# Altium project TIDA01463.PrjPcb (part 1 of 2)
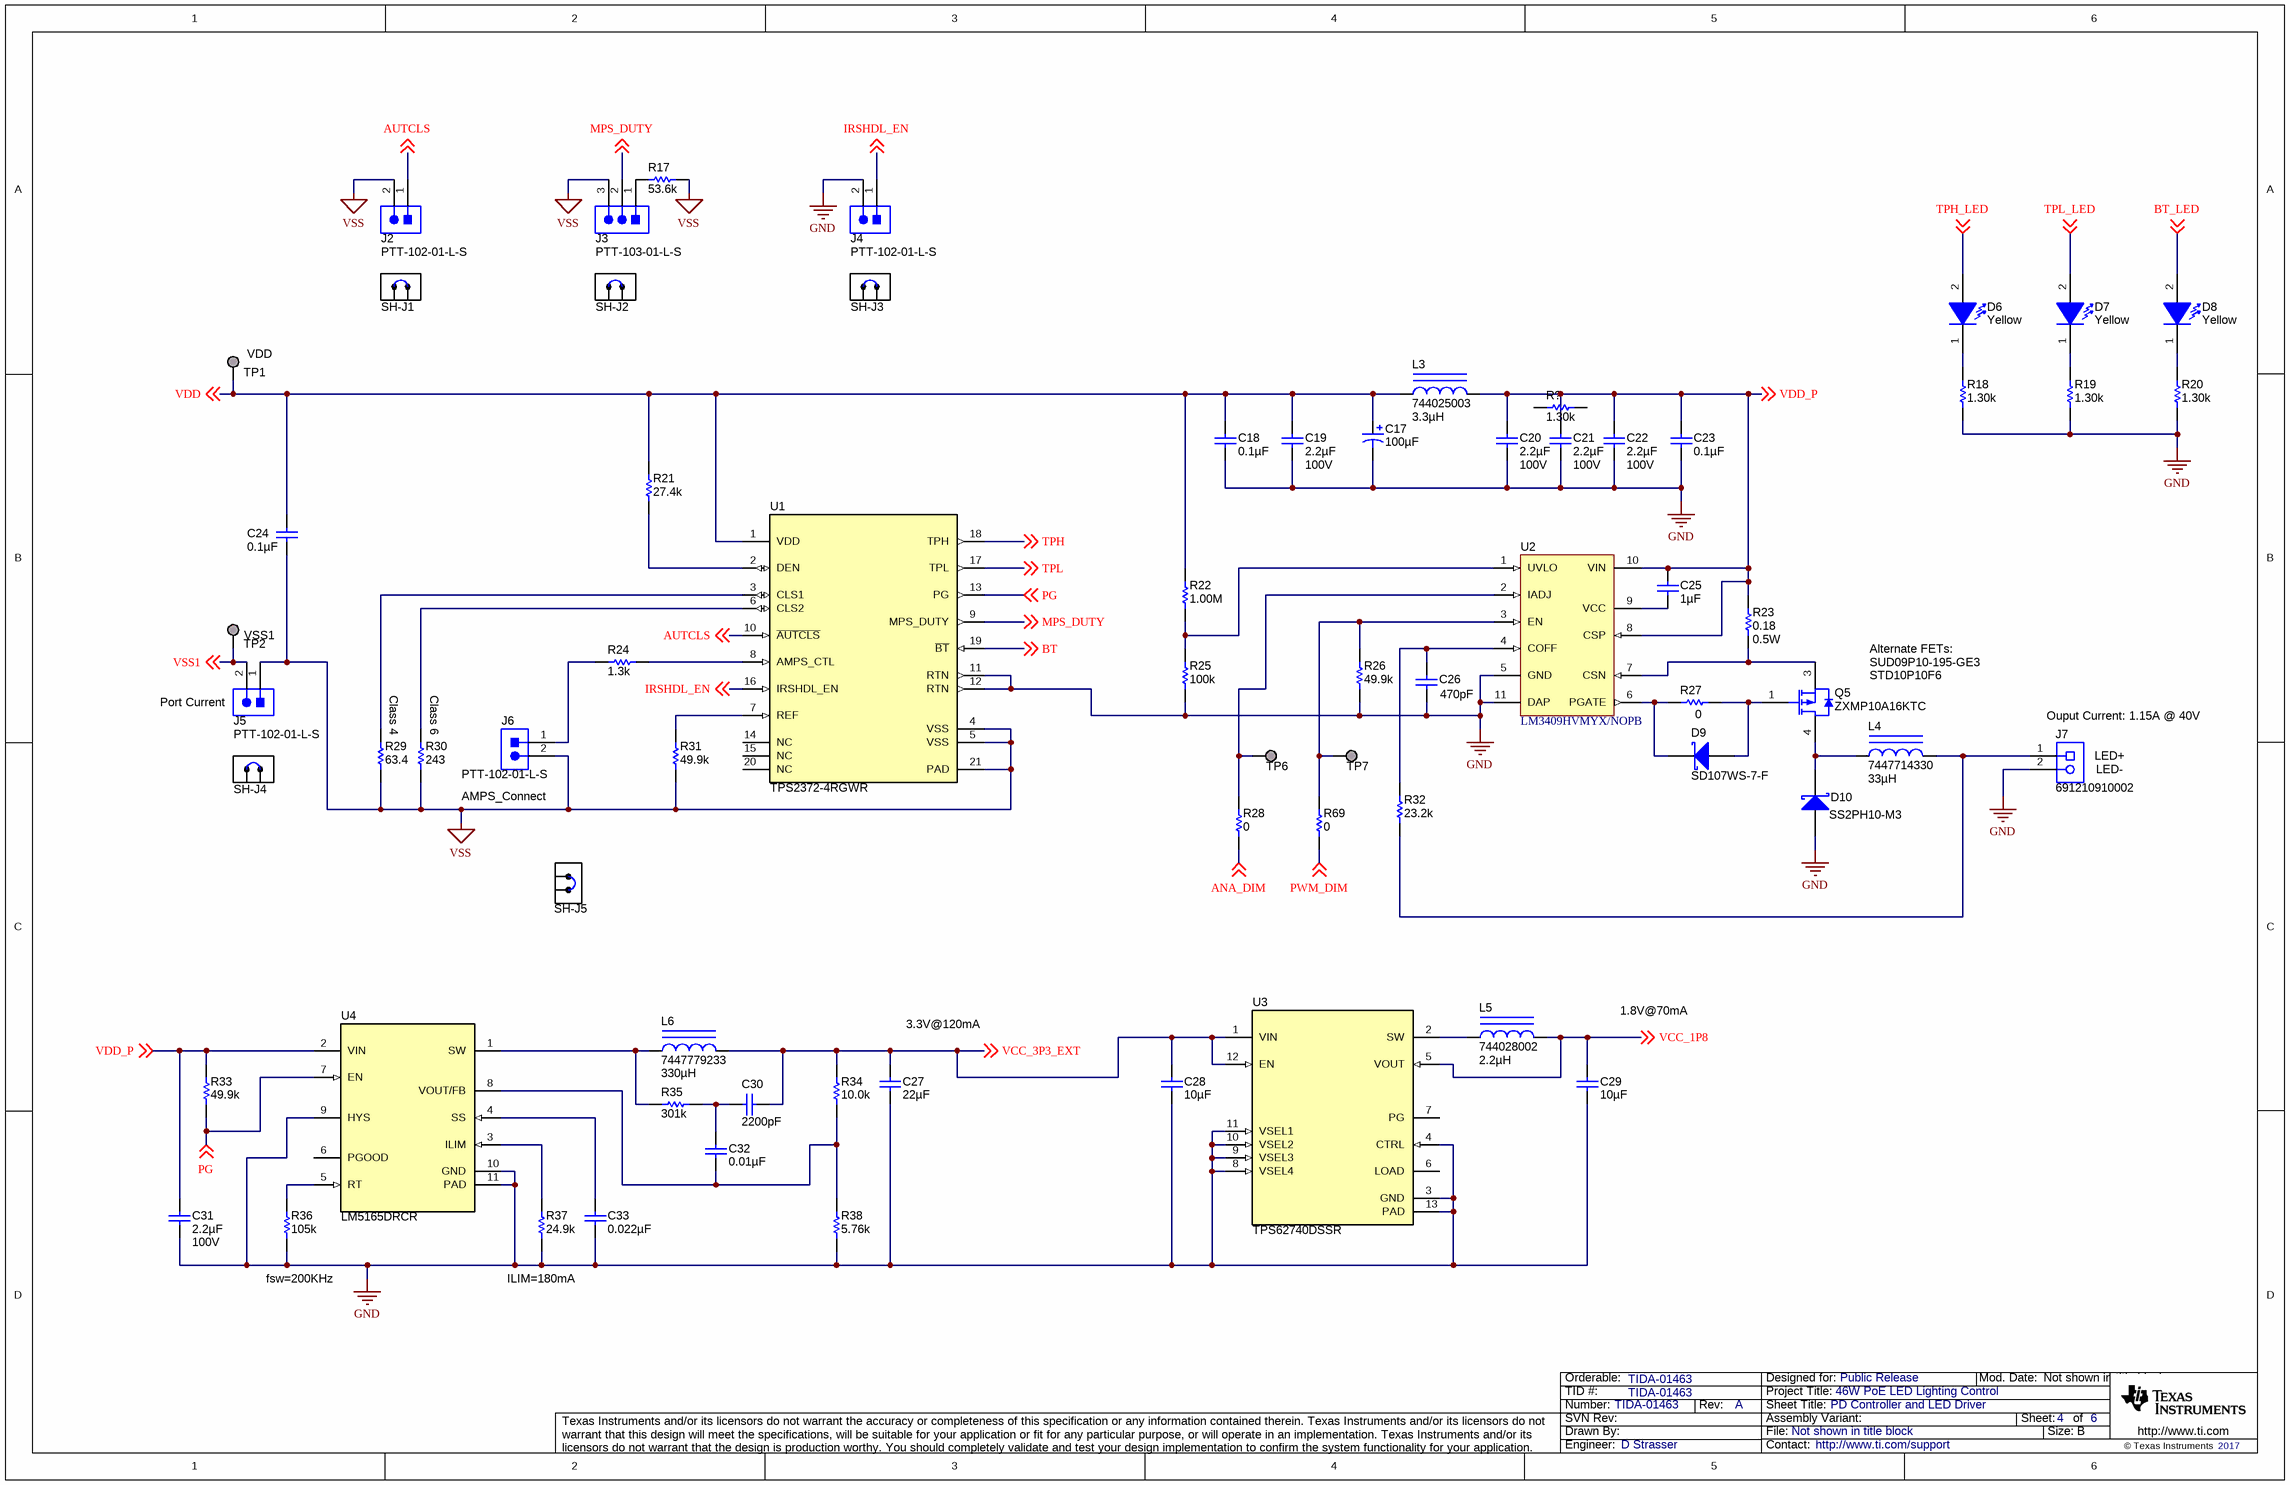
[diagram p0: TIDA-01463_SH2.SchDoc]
TID: TIDA-01463; TechSupport: http://www.ti.com/support; SCH_Rev: A; PRJ_Title: 46W PoE LED Lighting Control; PRJ_Number: TIDA-01463; PRJ_Engineer: D Strasser; PRJ_Customer: Public Release; PCB_Rev: A; PCB_Layout: D Strasser; EVM_orderable: TIDA-01463; CopyrightYear: 2017
5 sheets, 210 parts. Net scope: global (net labels, ports and power ports of the same name join across sheets).
Board file: TIDA-01463.PcbDoc
Sheets:
  TIDA-01463_SH2.SchDoc
  TIDA-01463_EVM_Hardware.SchDoc
  TIDA-01463_SH3.SchDoc
  TIDA-01463_SH4.SchDoc
  TIDA-01463_SH1.SchDoc

## Sheet TIDA-01463_SH2.SchDoc: PD Controller and LED Driver
size 431 x 279 mm; Date: Not shown in title block; ApprovedBy: Not shown in title block; CheckedBy: Not shown in title block; Author: Not shown in title block; CompanyName: Not shown in title block; Engineer: Not shown in title block; Organization: Not shown in title block; Address1: Not shown in title block; Address2: Not shown in title block; Address3: Not shown in title block; Address4: Not shown in title block; DocumentNumber: 4; Revision: Use project parameter SCH_Rev; SheetNumber: 4; SheetTotal: 6; PageSetup: Record=PageOptions¦CenterHorizontal=True¦CenterVertical=True¦PrintScale=1.00¦XCorrection=1.00¦YCorrection=1.00¦PrintKind=0¦BorderSize=5000000¦LeftOffset=0¦BottomOffset=0¦Orientation=2¦PaperLength=1000¦PaperWidth=1000¦Scale=100¦PaperSource=15¦PrintQuality=600¦MediaType=1¦DitherType=10¦PaperKind=Letter¦PrintScaleMode=1

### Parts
C17  ValueDisplayed: 100µF  [SM_RADIAL_J16]  (hidden comment: EEV-FK2A101M)
C18  ValueDisplayed: 0.1µF  [0805L]  (hidden comment: C0805C104K1RACTU)
C19  ValueDisplayed: 2.2µF  Value2: 100V  [1210_210L]  (hidden comment: C1210C225K1RACTU)
C20  ValueDisplayed: 2.2µF  Value2: 100V  [1210_210L]  (hidden comment: C1210C225K1RACTU)
C21  ValueDisplayed: 2.2µF  Value2: 100V  [1210_210L]  (hidden comment: C1210C225K1RACTU)
C22  ValueDisplayed: 2.2µF  Value2: 100V  [1210_210L]  (hidden comment: C1210C225K1RACTU)
C23  ValueDisplayed: 0.1µF  [0805_HV]  (hidden comment: C0805C104K1RACTU)
C24  ValueDisplayed: 0.1µF  [0805L]  (hidden comment: C0805C104K1RACTU)
C25  ValueDisplayed: 1µF  [0603L]  (hidden comment: 885012206052)
C26  ValueDisplayed: 470pF  [0603L]  (hidden comment: 06035A471JAT2A)
C27  ValueDisplayed: 22µF  [0805L]  (hidden comment: GRM21BR60J226ME39L)
C28  ValueDisplayed: 10µF  [0603L]  (hidden comment: GRM188R60J106ME47D)
C29  ValueDisplayed: 10µF  [0603L]  (hidden comment: GRM188R60J106ME47D)
C30  ValueDisplayed: 2200pF  [0603L]  (hidden comment: 885012206036)
C31  ValueDisplayed: 2.2µF  Value2: 100V  [1210_210L]  (hidden comment: C1210C225K1RACTU)
C32  ValueDisplayed: 0.01µF  [0603L]  (hidden comment: 885012206040)
C33  ValueDisplayed: 0.022µF  [0603L]  (hidden comment: 885012206091)
D6  value Yellow  [WL-SMCW_YELLOW]  (hidden comment: 150060YS75000)
D7  value Yellow  [WL-SMCW_YELLOW]  (hidden comment: 150060YS75000)
D8  value Yellow  [WL-SMCW_YELLOW]  (hidden comment: 150060YS75000)
D9  SD107WS-7-F  [sod-323]
D10  SS2PH10-M3  [DO-220AA]
J2  PTT-102-01-L-S  [Samtec_PTT-102-01-x-S]
J3  PTT-103-01-L-S  [Samtec_PTT-103-01-x-S]
J4  PTT-102-01-L-S  [Samtec_PTT-102-01-x-S]
J5  PTT-102-01-L-S  [Samtec_PTT-102-01-x-S]
J6  PTT-102-01-L-S  [Samtec_PTT-102-01-x-S]
J7  691210910002  [Wurth_691210910002]
L3  744025003  ValueDisplayed: 3.3µH  [WE-TPC_2828]
L4  7447714330  ValueDisplayed: 33µH  [WE-PD_1050]
L5  744028002  ValueDisplayed: 2.2µH  [WE-TPC-T]
L6  7447779233  ValueDisplayed: 330µH  [WE-PD_7345_PlasticBase]
Q5  ZXMP10A16KTC  [DPAK]
R17  ValueDisplayed: 53.6k  [0603L]  (hidden comment: CRCW060353K6FKEA)
R18  ValueDisplayed: 1.30k  [0603]  (hidden comment: RC0603FR-071K3L)
R19  ValueDisplayed: 1.30k  [0603]  (hidden comment: RC0603FR-071K3L)
R20  ValueDisplayed: 1.30k  [0603]  (hidden comment: RC0603FR-071K3L)
R21  ValueDisplayed: 27.4k  [0603L]  (hidden comment: CRCW060327K4FKEA)
R22  ValueDisplayed: 1.00M  [0402]  (hidden comment: CRCW04021M00FKED)
R23  ValueDisplayed: 0.18  Value2: 0.5W  [1210L]  (hidden comment: MCR25JZHFLR180)
R24  ValueDisplayed: 1.3k  [0805_HV]  (hidden comment: ERJ-6GEYJ132V)
R25  ValueDisplayed: 100k  [0402]  (hidden comment: CRCW0402100KFKED)
R26  ValueDisplayed: 49.9k  [0603L]  (hidden comment: CRCW060349K9FKEA)
R27  ValueDisplayed: 0  [0603L]  (hidden comment: CRCW06030000Z0EA)
R28  ValueDisplayed: 0  [0402]  (hidden comment: ERJ-2GE0R00X)
R29  ValueDisplayed: 63.4  [0603]  (hidden comment: RC0603FR-0763R4L)
R30  ValueDisplayed: 243  [0603]  (hidden comment: RC0603FR-07243RL)
R31  ValueDisplayed: 49.9k  [0603L]  (hidden comment: CRCW060349K9FKEA)
R32  ValueDisplayed: 23.2k  [0603L]  (hidden comment: CRCW060323K2FKEA)
R33  ValueDisplayed: 49.9k  [0603L]  (hidden comment: CRCW060349K9FKEA)
R34  ValueDisplayed: 10.0k  [0402]  (hidden comment: CRCW040210K0FKED)
R35  ValueDisplayed: 301k  [0603L]  (hidden comment: CRCW0603301KFKEA)
R36  ValueDisplayed: 105k  [0402]  (hidden comment: CRCW0402105KFKED)
R37  ValueDisplayed: 24.9k  [0402]  (hidden comment: CRCW040224K9FKED)
R38  ValueDisplayed: 5.76k  [0402]  (hidden comment: CRCW04025K76FKED)
R69  ValueDisplayed: 0  [0402]  (hidden comment: ERJ-2GE0R00X)
R?  ValueDisplayed: 1.30k  [0603]  (hidden comment: RC0603FR-071K3L)
SH-J1  2SN-BK-G  [2SN-BK-G]  (value not drawn)
SH-J2  2SN-BK-G  [2SN-BK-G]  (value not drawn)
SH-J3  2SN-BK-G  [2SN-BK-G]  (value not drawn)
SH-J4  2SN-BK-G  [2SN-BK-G]  (value not drawn)
SH-J5  2SN-BK-G  [2SN-BK-G]  (value not drawn)
TP1  TESTPOINT  [Keystone_5019]  (value not drawn)
TP2  TESTPOINT  [Keystone_5019]  (value not drawn)
TP6  TESTPOINT  [PAD_1MM_SQUARE]  (value not drawn)  (no BOM)
TP7  TESTPOINT  [PAD_1MM_SQUARE]  (value not drawn)  (no BOM)
U1  TPS2372-4RGWR  [RGW0020B]
U2  LM3409HVMYX/NOPB  [MUC10A_N]
U3  TPS62740DSSR  [DSS0012A]
U4  LM5165DRCR  [DRC0010J]

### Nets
GND: C17.2(-) C18.2 C19.2 C20.2 C21.2 C22.2 C23.2 C26.2 C27.2 C28.2 C29.2 C31.2 C33.2 D10.2(A) J4.2 J7.2 R18.1 R19.1 R20.1 R25.1 R26.1 R36.1 R37.1 R38.1 U1.11(RTN) U1.12(RTN) U2.5(GND) U2.11(DAP) U3.3(GND) U3.4(CTRL) U3.8(VSEL4) U3.9(VSEL3) U3.10(VSEL2) U3.11(VSEL1) U3.13(PAD) U4.9(HYS) U4.10(GND) U4.11(PAD)
VSS: C24.2 J2.2 J3.3 J5.1 J6.2 R17.2 R29.1 R30.1 R31.2 U1.4(VSS) U1.5(VSS) U1.21(PAD)
ANA_DIM: R28.1 ; off-sheet ANA_DIM
AUTCLS: J2.1 U1.10(~{AUTCLS}) ; off-sheet AUTCLS
BT: U1.19(~{BT}) ; off-sheet BT
BT_LED: D8.2(A) ; off-sheet BT_LED
IRSHDL_EN: J4.1 U1.16(IRSHDL_EN) ; off-sheet IRSHDL_EN
MPS_DUTY: J3.2 U1.9(MPS_DUTY) ; off-sheet MPS_DUTY
PG: R33.1 U1.13(PG) U4.7(EN) ; off-sheet PG
PWM_DIM: R69.1 ; off-sheet PWM_DIM
TPH: U1.18(TPH) ; off-sheet TPH
TPH_LED: D6.2(A) ; off-sheet TPH_LED
TPL: U1.17(TPL) ; off-sheet TPL
TPL_LED: D7.2(A) ; off-sheet TPL_LED
VCC_1P8: C29.1 L5.2 U3.5(VOUT) ; off-sheet VCC_1P8
VCC_3P3_EXT: C27.1 C28.1 C30.1 L6.2 R34.2 U3.1(VIN) U3.12(EN) ; off-sheet VCC_3P3_EXT
VDD: C17.1(+) C18.1 C19.1 C24.1 L3.1 R21.2 R22.2 TP1.1 U1.1(VDD) ; off-sheet VDD
VDD_P: C20.1 C21.1 C22.1 C23.1 C25.1 C31.1 L3.2 R23.2 R33.2 U2.8(CSP) U2.10(VIN) U4.2(VIN) ; off-sheet VDD_P
VSS1: J5.2 TP2.1 ; off-sheet VSS1
NetC25_2: C25.2 U2.9(VCC)
NetC26_1: C26.1 R32.2 U2.4(COFF)
NetC30_2: C30.2 C32.1 R35.2
NetC32_2: C32.2 R34.1 R38.2 U4.8(VOUT/FB)
NetC33_1: C33.1 U4.4(SS)
NetD6_1: D6.1(K) R18.2
NetD7_1: D7.1(K) R19.2
NetD8_1: D8.1(K) R20.2
NetD9_1: D9.1(K) R27.1 U2.6(PGATE)
NetD9_2: D9.2(A) Q5.1(G) R27.2
NetD10_1: D10.1(K) L4.1 Q5.4(D)
NetJ3_1: J3.1 R17.1
NetJ6_1: J6.1 R24.1
NetJ7_1: J7.1 L4.2 R32.1
NetL5_1: L5.1 U3.2(SW)
NetL6_1: L6.1 R35.1 U4.1(SW)
NetQ5_3: Q5.3(S) R23.1 U2.7(CSN)
NetR21_1: R21.1 U1.2(DEN)
NetR22_1: R22.1 R25.2 U2.1(UVLO)
NetR24_2: R24.2 U1.8(AMPS_CTL)
NetR26_2: R26.2 R69.2 TP7.1 U2.3(EN)
NetR28_2: R28.2 TP6.1 U2.2(IADJ)
NetR29_2: R29.2 U1.3(CLS1)
NetR30_2: R30.2 U1.6(CLS2)
NetR31_1: R31.1 U1.7(REF)
NetR36_2: R36.2 U4.5(RT)
NetR37_2: R37.2 U4.3(ILIM)

Not connected (* = marked no-connect by the designer): R? 1 2; U1 14(NC) 15(NC) 20(NC); U3 6(LOAD) 7(PG); U4 6(PGOOD)

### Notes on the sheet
- (near TP1) VDD
- (near TP2) VSS1
- (near J5) Port Current
- Alternate FETs:
- SUD09P10-195-GE3
- STD10P10F6
- (near R29) Class 4
- (near R30) Class 6
- (near J7) LED-
- (near J7) LED+
- (near J7) Ouput Current: 1.15A @ 40V
- AMPS_Connect
- (near C27) 3.3V@120mA
- 1.8V@70mA
- (near R36) fsw=200KHz
- ILIM=180mA

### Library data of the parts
C17 = EEV-FK2A101M: CAP, AL, 100 µF, 100 V, +/- 20%, 0.17 ohm, SMD; Manufacturer: Panasonic; Polarized: Y; CompType: Capacitor; Value: 100uF; U/M: EA; Cap_F: 0.0001; Tolerance_%: 20; VDC_V: 100; Value2: 100V; ESR_ohm: 0.17; IRMS_A: 0.793; TaMin_C: -55; TaMax_C: 105; Cap_Case: J16; AEC Category: Q200
C18 C23 C24 = C0805C104K1RACTU: CAP, CERM, 0.1 µF, 100 V, +/- 10%, X7R, 0805; Manufacturer: Kemet; Polarized: N; CompType: Capacitor; Value: 0.1uF; U/M: EA; Cap_F: 0.0000001; Tolerance_%: 10; ESR_ohm: 0.064; Value1: 0.064 ohm; VDC_V: 100; Value2: 100V; IRMS_A: 1.64; TaMin_C: -55; TaMax_C: 125; Cap_Case: 0805; AEC Category: Q200
C19-C22 C31 = C1210C225K1RACTU: CAP, CERM, 2.2 µF, 100 V, +/- 10%, X7R, 1210; Manufacturer: Kemet; Polarized: N; CompType: Capacitor; Value: 2.2uF; U/M: EA; Cap_F: 0.0000022; Tolerance_%: 10; Value1: Unknown; VDC_V: 100; TaMin_C: -55; TaMax_C: 125; Cap_Case: 1210; AEC Category: Q200; SizeArea_mm2: 8; SizeAreaWB_mm2: 14.7; SizeX_mm: 3.2; SizeY_mm: 2.5; SizeZ_mm: 2.1
C25 = 885012206052: CAP, CERM, 1 µF, 16 V, +/- 10%, X7R, 0603; Manufacturer: Wurth Elektronik; Polarized: N; CompType: Capacitor; Value: 1uF; U/M: EA; Cap_F: 0.000001; Tolerance_%: 10; Value1: Unknown; VDC_V: 16; Value2: 16V; TaMin_C: -55; TaMax_C: 125; Cap_Case: 0603; AEC Category: Q200
C26 = 06035A471JAT2A: CAP, CERM, 470 pF, 50 V, +/- 5%, C0G/NP0, 0603; Manufacturer: AVX; Polarized: N; CompType: Capacitor; Value: 470pF; U/M: EA; Cap_F: 0.00000000047; Tolerance_%: 5; ESR_ohm: 0.063; Value1: 0.063 ohm; VDC_V: 50; Value2: 50V; TaMin_C: -55; TaMax_C: 125; Cap_Case: 0603; AEC Category: Q200
C27 = GRM21BR60J226ME39L: CAP, CERM, 22 µF, 6.3 V, +/- 20%, X5R, 0805; Manufacturer: MuRata; Polarized: N; CompType: Capacitor; Value: 22uF; U/M: EA; Cap_F: 0.000022; Tolerance_%: 20; ESR_ohm: 0.009; Value1: 0.009 ohm; VDC_V: 6.3; Value2: 6.3V; IRMS_A: 3.5; TaMin_C: -55; TaMax_C: 85; Cap_Case: 0805; SizeArea_mm2: 2.5; SizeAreaWB_mm2: 6.75; SizeX_mm: 2; SizeY_mm: 1.25; SizeZ_mm: 1.45; AEC Category: Q200
C28 C29 = GRM188R60J106ME47D: CAP, CERM, 10 µF, 6.3 V, +/- 20%, X5R, 0603; Manufacturer: MuRata; Polarized: N; CompType: Capacitor; Value: 10uF; U/M: EA; Cap_F: 0.00001; Tolerance_%: 20; ESR_ohm: 0.009; Value1: 0.009 ohm; VDC_V: 6.3; Value2: 6.3V; IRMS_A: 2.74; TaMin_C: -55; TaMax_C: 125; Cap_Case: 0603; SizeArea_mm2: 1.28; SizeAreaWB_mm2: 4.68; SizeX_mm: 1.6; SizeY_mm: 0.8; SizeZ_mm: 1; AEC Category: Q200
C30 = 885012206036: CAP, CERM, 2200 pF, 16 V, +/- 10%, X7R, 0603; Manufacturer: Wurth Elektronik; Polarized: N; CompType: Capacitor; Value: 2200pF; U/M: EA; Cap_F: 0.0000000022; Tolerance_%: 10; Value1: Unknown; VDC_V: 16; Value2: 16V; TaMin_C: -55; TaMax_C: 125; Cap_Case: 0603; SizeArea_mm2: 1.28; SizeAreaWB_mm2: 4.68; SizeX_mm: 1.6; SizeY_mm: 0.8; SizeZ_mm: 1; AEC Category: Q200
C32 = 885012206040: CAP, CERM, 0.01 µF, 16 V, +/- 10%, X7R, 0603; Manufacturer: Wurth Elektronik; Polarized: N; CompType: Capacitor; Value: 0.01uF; U/M: EA; Cap_F: 0.00000001; Tolerance_%: 10; Value1: Unknown; VDC_V: 16; Value2: 16V; TaMin_C: -55; TaMax_C: 125; Cap_Case: 0603; SizeArea_mm2: 1.28; SizeAreaWB_mm2: 4.68; SizeX_mm: 1.6; SizeY_mm: 0.8; SizeZ_mm: 1; AEC Category: Q200
C33 = 885012206091: CAP, CERM, 0.022 µF, 50 V, +/- 10%, X7R, 0603; Manufacturer: Wurth Elektronik; Polarized: N; CompType: Capacitor; Value: 0.022uF; U/M: EA; Cap_F: 0.000000022; Tolerance_%: 10; Value1: Unknown; VDC_V: 50; Value2: 50V; TaMin_C: -55; TaMax_C: 125; Cap_Case: 0603; SizeArea_mm2: 1.28; SizeAreaWB_mm2: 4.68; SizeX_mm: 1.6; SizeY_mm: 0.8; SizeZ_mm: 1; AEC Category: Q200
D6-D8 = 150060YS75000: LED, Yellow, SMD; Manufacturer: Wurth Elektronik; Type: AlInGaP; Vf_V: 2; Value2: 2V; Io_A: 0.02; Value1: W; U/M: EA
D9 = SD107WS-7-F: Diode, Schottky, 30 V, 0.1 A, SOD-323; Manufacturer: Diodes Inc.; U/M: EA; Vf_V: 0.5; Value: 30V; Value1: 0.1A; Value2: 0.5V; Io_A: 0.1; Vr_V: 30; AEC Category: Q101
D10 = SS2PH10-M3: Diode, Schottky, 100 V, 2 A, DO-220AA; Manufacturer: Vishay-Semiconductor; U/M: EA; Vf_V: 0.62; Value: 100V; Value1: 2A; Value2: 0.62V; Io_A: 2; Vr_V: 100; TJmax_C: 175; RJC_CperW: 25; AEC Category: Q101
J2 J4-J6 = PTT-102-01-L-S: Header, 2mm, 2x1, Gold, TH; Manufacturer: Samtec; SymbolCreator: a0412235; Pitch_mm: 2; Gender: Male; Shrouded: N; Current_A: 2.9; Cert_UL: Y
J3 = PTT-103-01-L-S: Header, 2mm, 3x1, Gold, TH; Manufacturer: Samtec; SymbolCreator: a0799628; Pitch_mm: 2; Gender: Male; Shrouded: N; Current_A: 2.9; Cert_UL: Y
J7 = 691210910002: Receptacle, 2.54mm, 2x1, Tin, R/A, TH; Manufacturer: Wurth Elektronik; SymbolCreator: a0412235; Pitch_mm: 2.54; Gender: Female; Row_Count: 1; Current_A: 6; Voltage_V: 150; Cert_UL: Y
L3 = 744025003: Inductor, Shielded Drum Core, Ferrite, 3.3 µH, 1.5 A, 0.085 ohm, SMD; Manufacturer: Wurth Elektronik; Value: 3.3uH; Ind_H: 3.3E-6; Imax_A: 1.5; Irms: 1.5A @ 40C rise; Isat: 1.8A @ 35% inductance drop; DCR_ohm: 0.085; Value2: 1.5A; SizeAreaWB_mm2: 14.44; SizeArea_mm2: 7.84; SizeX_mm: 2.8; SizeZ_mm: 3; AEC Category: Q200
L4 = 7447714330: Inductor, Shielded Drum Core, Ferrite, 33 µH, 2.5 A, 0.066 ohm, SMD; Manufacturer: Wurth Elektronik; Value: 33uH; Ind_H: 33.0E-6; Imax_A: 2.5; Irms: 2.5A @ 40C rise; Isat: 2.9A @ 10% inductance drop; DCR_ohm: 0.066; Value2: 2.5A; SizeAreaWB_mm2: 144; SizeArea_mm2: 100; SizeX_mm: 10; SizeZ_mm: 5; AEC Category: Q200
L5 = 744028002: Inductor, Shielded Drum Core, Ferrite, 2.2 µH, 1 A, 0.125 ohm, SMD; Manufacturer: Wurth Elektronik; Value: 2.2uH; Ind_H: 2.2E-6; Imax_A: 1; Irms: 1.5A @ 40C rise; Isat: 1A @ 35% inductance drop; DCR_ohm: 0.125; Value2: 1A; SizeAreaWB_mm2: 14.44; SizeArea_mm2: 7.84; SizeX_mm: 2.8; SizeZ_mm: 1.1; AEC Category: Q200
L6 = 7447779233: Inductor, Shielded Drum Core, Metal Composite, 330 µH, 0.39 A, 1.15 ohm, SMD; Manufacturer: Wurth Elektronik; Value: 330uH; Ind_H: 330.0E-6; Imax_A: 0.39; Irms: 0.39A @ 40C rise; Isat: 0.45A @ 10% inductance drop; DCR_ohm: 1.15; Value2: 0.39A; SizeAreaWB_mm2: 86.49; SizeArea_mm2: 53.29; SizeX_mm: 7.3; SizeZ_mm: 4.5; AEC Category: Q200
Q5 = ZXMP10A16KTC: MOSFET, P-CH, -100 V, 3 A, DPAK; Manufacturer: Diodes Inc.; Alternate Manufacturer: None; U/M: EA; ChType: P; Value: -100V; Value1: ? ohm; Value2: 16.5 nC; QgTyp_nC: 16.5; Vgs_V: 20; IdsMax_A: 3; AEC Category: Q101; AEC Qualified: N
R17 = CRCW060353K6FKEA: RES, 53.6 k, 1%, 0.1 W, 0603; Manufacturer: Vishay-Dale; CompType: Resistor; Value: 53.6k; Res_ohm: 53600; Value_Code: 53k6; Tolerance_%: 1; Power_W: 0.1; Value2: 0.1W; VDC_V: 75; TempCo: 100 ppm/C; EIA_Code: E96; U/M: EA; AEC Category: Q200
R18-R20 R? = RC0603FR-071K3L: RES, 1.30 k, 1%, 0.1 W, 0603; Manufacturer: Yageo America; CompType: Resistor; Value: 1.30k; Res_ohm: 1300; Value_Code: 1k30; Tolerance_%: 1; Power_W: 0.1; Value2: 0.1W; VDC_V: 150; TempCo: 200 ppm/C; SizeArea_mm2: 1.28; SizeX_mm: 1.6; SizeY_mm: 0.8; EIA_Code: E96; U/M: EA; AEC Category: Q200
R21 = CRCW060327K4FKEA: RES, 27.4 k, 1%, 0.1 W, 0603; Manufacturer: Vishay-Dale; CompType: Resistor; Value: 27.4k; Res_ohm: 27400; Value_Code: 27k4; Tolerance_%: 1; Power_W: 0.1; Value2: 0.1W; VDC_V: 75; TempCo: 100 ppm/C; EIA_Code: E96; U/M: EA; AEC Category: Q200
R22 = CRCW04021M00FKED: RES, 1.00 M, 1%, 0.063 W, 0402; Manufacturer: Vishay-Dale; CompType: Resistor; Value: 1.00Meg; Res_ohm: 1000000; Value_Code: 1M00; Tolerance_%: 1; Power_W: 0.063; Value2: 0.063W; VDC_V: 50; TempCo: 100 ppm/C; EIA_Code: E96; U/M: EA; AEC Category: Q200; SizeArea_mm2: 0.5; SizeZ_mm: 0.6
R23 = MCR25JZHFLR180: RES, 0.18, 1%, 0.5 W, 1210; Manufacturer: Rohm; CompType: Resistor; Value: 0.18; Value_Code: R180; Tolerance_%: 1; Power_W: 0.5; VDC_V: 0; TempCo: 200 ppm/C; EIA_Code: E96; U/M: EA; AEC Category: Q200; SizeArea_mm2: 8; SizeX_mm: 3.2; SizeY_mm: 2.5; SizeZ_mm: 1.35; SizeAreaWB_mm2: 14.7
R24 = ERJ-6GEYJ132V: RES, 1.3 k, 5%, 0.125 W, 0805; Manufacturer: Panasonic; CompType: Resistor; Value: 1.3k; Res_ohm: 1300; Value_Code: 1k30; Tolerance_%: 5; Power_W: 0.125; Value2: 0.125W; VDC_V: 150; TempCo: 200 ppm/C; SizeArea_mm2: 2.5; SizeX_mm: 2; SizeY_mm: 1.25; SizeZ_mm: 1.45; EIA_Code: E24; U/M: EA; AEC Category: Q200
R25 = CRCW0402100KFKED: RES, 100 k, 1%, 0.063 W, 0402; Manufacturer: Vishay-Dale; CompType: Resistor; Value: 100k; Res_ohm: 100000; Tolerance_%: 1; Power_W: 0.063; Value2: 0.063W; VDC_V: 50; TempCo: 100 ppm/C; EIA_Code: E96; U/M: EA; AEC Category: Q200; SizeArea_mm2: 0.5; SizeZ_mm: 0.6
R26 R31 R33 = CRCW060349K9FKEA: RES, 49.9 k, 1%, 0.1 W, 0603; Manufacturer: Vishay-Dale; CompType: Resistor; Value: 49.9k; Res_ohm: 49900; Value_Code: 49k9; Tolerance_%: 1; Power_W: 0.1; Value2: 0.1W; VDC_V: 75; TempCo: 100 ppm/C; EIA_Code: E96; U/M: EA; AEC Category: Q200
R27 = CRCW06030000Z0EA: RES, 0, 5%, 0.1 W, 0603; Manufacturer: Vishay-Dale; CompType: Resistor; Value: 0; Value_Code: 0000; Tolerance_%: 5; Power_W: 0.1; Value2: 0.1W; VDC_V: 75; TempCo: 200 ppm/C; EIA_Code: E24; U/M: EA; AEC Category: Q200
R28 R69 = ERJ-2GE0R00X: RES, 0, 5%, 0.063 W, 0402; Manufacturer: Panasonic; CompType: Resistor; Value: 0; Value_Code: 0000; Tolerance_%: 5; Power_W: 0.063; Value2: 0.063W; VDC_V: 50; TempCo: 600 ppm/C; SizeArea_mm2: 0.5; SizeX_mm: 1; SizeZ_mm: 0.6; EIA_Code: E24; U/M: EA; AEC Category: Q200
R29 = RC0603FR-0763R4L: RES, 63.4, 1%, 0.1 W, 0603; Manufacturer: Yageo America; CompType: Resistor; Value: 63.4; Value_Code: 63R4; Tolerance_%: 1; Power_W: 0.1; Value2: 0.1W; VDC_V: 150; TempCo: 200 ppm/C; SizeArea_mm2: 1.28; SizeX_mm: 1.6; SizeY_mm: 0.8; EIA_Code: E96; U/M: EA; AEC Category: Q200
R30 = RC0603FR-07243RL: RES, 243, 1%, 0.1 W, 0603; Manufacturer: Yageo America; CompType: Resistor; Value: 243; Value_Code: 243R; Tolerance_%: 1; Power_W: 0.1; Value2: 0.1W; VDC_V: 150; TempCo: 200 ppm/C; SizeArea_mm2: 1.28; SizeX_mm: 1.6; SizeY_mm: 0.8; EIA_Code: E96; U/M: EA; AEC Category: Q200
R32 = CRCW060323K2FKEA: RES, 23.2 k, 1%, 0.1 W, 0603; Manufacturer: Vishay-Dale; CompType: Resistor; Value: 23.2k; Res_ohm: 23200; Value_Code: 23k2; Tolerance_%: 1; Power_W: 0.1; Value2: 0.1W; VDC_V: 75; TempCo: 100 ppm/C; EIA_Code: E96; U/M: EA; AEC Category: Q200
R34 = CRCW040210K0FKED: RES, 10.0 k, 1%, 0.063 W, 0402; Manufacturer: Vishay-Dale; CompType: Resistor; Value: 10.0k; Res_ohm: 10000; Value_Code: 10k0; Tolerance_%: 1; Power_W: 0.063; Value2: 0.063W; VDC_V: 50; TempCo: 100 ppm/C; SizeArea_mm2: 0.5; SizeZ_mm: 0.6; EIA_Code: E96; U/M: EA; AEC Category: Q200
R35 = CRCW0603301KFKEA: RES, 301 k, 1%, 0.1 W, 0603; Manufacturer: Vishay-Dale; CompType: Resistor; Value: 301k; Res_ohm: 301000; Tolerance_%: 1; Power_W: 0.1; Value2: 0.1W; VDC_V: 75; TempCo: 100 ppm/C; SizeArea_mm2: 1.28; SizeX_mm: 1.6; SizeY_mm: 0.8; EIA_Code: E96; U/M: EA; AEC Category: Q200
R36 = CRCW0402105KFKED: RES, 105 k, 1%, 0.063 W, 0402; Manufacturer: Vishay-Dale; CompType: Resistor; Value: 105k; Res_ohm: 105000; Tolerance_%: 1; Power_W: 0.063; Value2: 0.063W; VDC_V: 50; TempCo: 100 ppm/C; SizeArea_mm2: 0.5; SizeZ_mm: 0.6; EIA_Code: E96; U/M: EA; AEC Category: Q200
R37 = CRCW040224K9FKED: RES, 24.9 k, 1%, 0.063 W, 0402; Manufacturer: Vishay-Dale; CompType: Resistor; Value: 24.9k; Res_ohm: 24900; Value_Code: 24k9; Tolerance_%: 1; Power_W: 0.063; Value2: 0.063W; VDC_V: 50; TempCo: 100 ppm/C; SizeArea_mm2: 0.5; SizeZ_mm: 0.6; EIA_Code: E96; U/M: EA; AEC Category: Q200
R38 = CMP-0026468-1: RES, 5.76 k, 1%, 0.063 W, 0402; Manufacturer: Vishay-Dale; Power_W: 63mW; TempCo: 100 ppm/C; Value_Code: 5k76; U/M: EA; Value: 5.76k; EIA_Code: E96; SizeX_mm: 1; SizeY_mm: 0.5; SizeZ_mm: 0.6; Value2: 0.063W; VDC_V: 50V; AEC Category: Q200
SH-J1-SH-J5 = 2SN-BK-G: Shunt, 2mm, Gold plated, Black; Manufacturer: Samtec; Value: 1x2; Note: You can "mate" this to a header by matching the designator.  i.e. use SH-J3 for header J3
TP1 TP2 = 5019: Test Point, Miniature, SMT; Manufacturer: Keystone; CompType: Test Point Loop; U/M: EA
TP6 TP7 = PAD_1MM_SQUARE: 1.0x1.0mm pad, square, SMD; Manufacturer: Any
U1 = CMP-0013753-2: Mid Power bt PoE PD Interface with Automatic Maintain Power Signature, Advanced Startup and Ultra-Low Standby Power, RGW0020B (VQFN-20); Manufacturer: Texas Instruments; Alternate PartNumber: TPS2372-4RGWT; SizeX_mm: 5; CompType: IC; SizeZ_mm: 1; SizeArea_mm2: 25; SizeAreaWB_mm2: 49; U/M: EA
U2 = LM3409HVMYX/NOPB: PFET Buck Controller for High Power LED Drives, 10-pin eMSOP, Pb-Free; Manufacturer: Texas Instruments; PackageTopMarking: ZXTT*SYHB; PowerWise: Y; CompType: MiscPower
U3 = TPS62740DSSR: 360nA IQ Step Down Converter for Low Power Applications, DSS0012A (WSON-12); Alternate PartNumber: TPS62740DSST; Manufacturer: Texas Instruments; SymbolCreator: Altium; SizeArea_mm2: 6; SizeAreaWB_mm2: 12; SizeX_mm: 2; SizeY_mm: 3; SizeZ_mm: 0.8; CompType: IC; U/M: EA
U4 = LM5165DRCR: 3V-65V, 150mA Synchronous Buck Converter With Ultra-Low IQ, DRC0010J (VSON-10); Alternate PartNumber: LM5165DRCT; Manufacturer: Texas Instruments; SymbolCreator: Altium; SizeArea_mm2: 9; SizeAreaWB_mm2: 16; SizeX_mm: 3; SizeZ_mm: 1; CompType: IC; U/M: EA

## Sheet TIDA-01463_EVM_Hardware.SchDoc: Hardware
size 431 x 279 mm; Date: Not shown in title block; ApprovedBy: Not shown in title block; CheckedBy: Not shown in title block; Author: Not shown in title block; CompanyName: Not shown in title block; Engineer: Not shown in title block; Organization: Not shown in title block; Address1: Not shown in title block; Address2: Not shown in title block; Address3: Not shown in title block; Address4: Not shown in title block; DocumentNumber: 2; Revision: Use project parameter SCH_Rev; SheetNumber: 2; SheetTotal: 6; PageSetup: Record=PageOptions¦CenterHorizontal=True¦CenterVertical=True¦PrintScale=1.00¦XCorrection=1.00¦YCorrection=1.00¦PrintKind=0¦BorderSize=5000000¦LeftOffset=0¦BottomOffset=0¦Orientation=2¦PaperLength=1000¦PaperWidth=1000¦Scale=100¦PaperSource=15¦PrintQuality=600¦MediaType=1¦DitherType=10¦PaperKind=Letter¦PrintScaleMode=1
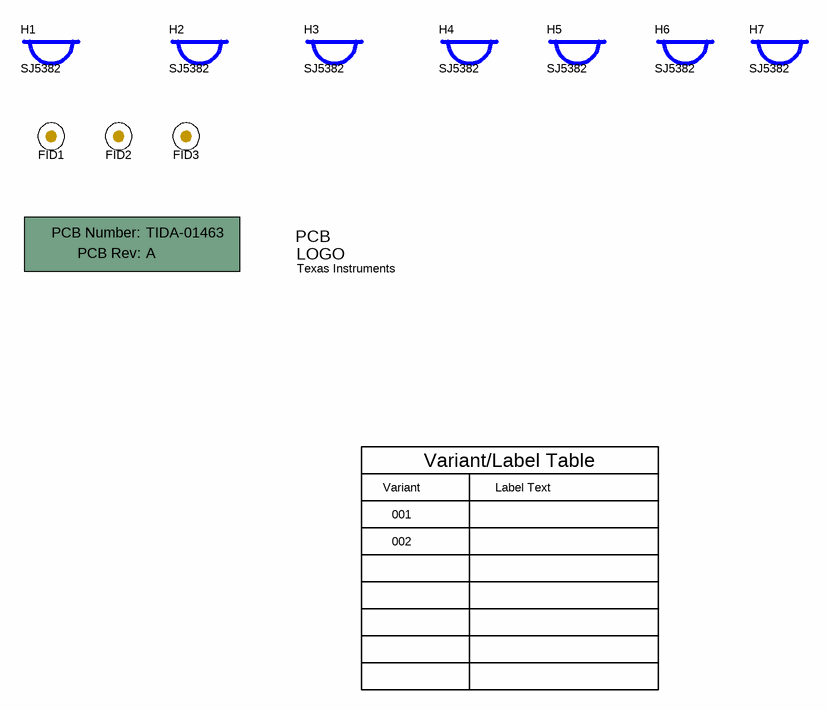
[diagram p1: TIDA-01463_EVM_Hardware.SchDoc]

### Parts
!PCB1  Printed Circuit Board  (value not drawn)  (mechanical)
FID1  Fiducial  [Fiducial10-20]  (value not drawn)
FID2  Fiducial  [Fiducial10-20]  (value not drawn)
FID3  Fiducial  [Fiducial10-20]  (value not drawn)
H1  SJ5382  [3M_SJ5382]
H2  SJ5382  [3M_SJ5382]
H3  SJ5382  [3M_SJ5382]
H4  SJ5382  [3M_SJ5382]
H5  SJ5382  [3M_SJ5382]
H6  SJ5382  [3M_SJ5382]
H7  SJ5382  [3M_SJ5382]
Logo1  Texas Instruments  [TI_Stacked_Overlay_Small]  (no BOM)

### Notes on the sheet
- Variant
- Variant/Label Table
- Label Text
- 001
- 002

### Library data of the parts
!PCB1 = PCB: Manufacturer: Any; PartNumber: TIDA-01463; SymbolCreator: a0412235
FID1-FID3 = Fiducial: Fiducial mark.  There is nothing to buy or mount.; SymbolCreator: codlsc
H1-H7 = SJ5382: Bumpon, Hemisphere, 0.25 X 0.075, Clear; Manufacturer: 3M; SymbolCreator: a0412235
Logo1 = TI_Logo: Texas Instrument Corporate Signature; SymbolCreator: codlsc

## Sheet TIDA-01463_SH3.SchDoc: MCU
size 431 x 279 mm; Date: Not shown in title block; ApprovedBy: Not shown in title block; CheckedBy: Not shown in title block; Author: Not shown in title block; CompanyName: Not shown in title block; Engineer: Not shown in title block; Organization: Not shown in title block; Address1: Not shown in title block; Address2: Not shown in title block; Address3: Not shown in title block; Address4: Not shown in title block; DocumentNumber: 5; Revision: Use project parameter SCH_Rev; SheetNumber: 5; SheetTotal: 6; PageSetup: Record=PageOptions¦CenterHorizontal=True¦CenterVertical=True¦PrintScale=1.00¦XCorrection=1.00¦YCorrection=1.00¦PrintKind=0¦BorderSize=5000000¦LeftOffset=0¦BottomOffset=0¦Orientation=2¦PaperLength=1000¦PaperWidth=1000¦Scale=100¦PaperSource=15¦PrintQuality=600¦MediaType=1¦DitherType=10¦PaperKind=Letter¦PrintScaleMode=1
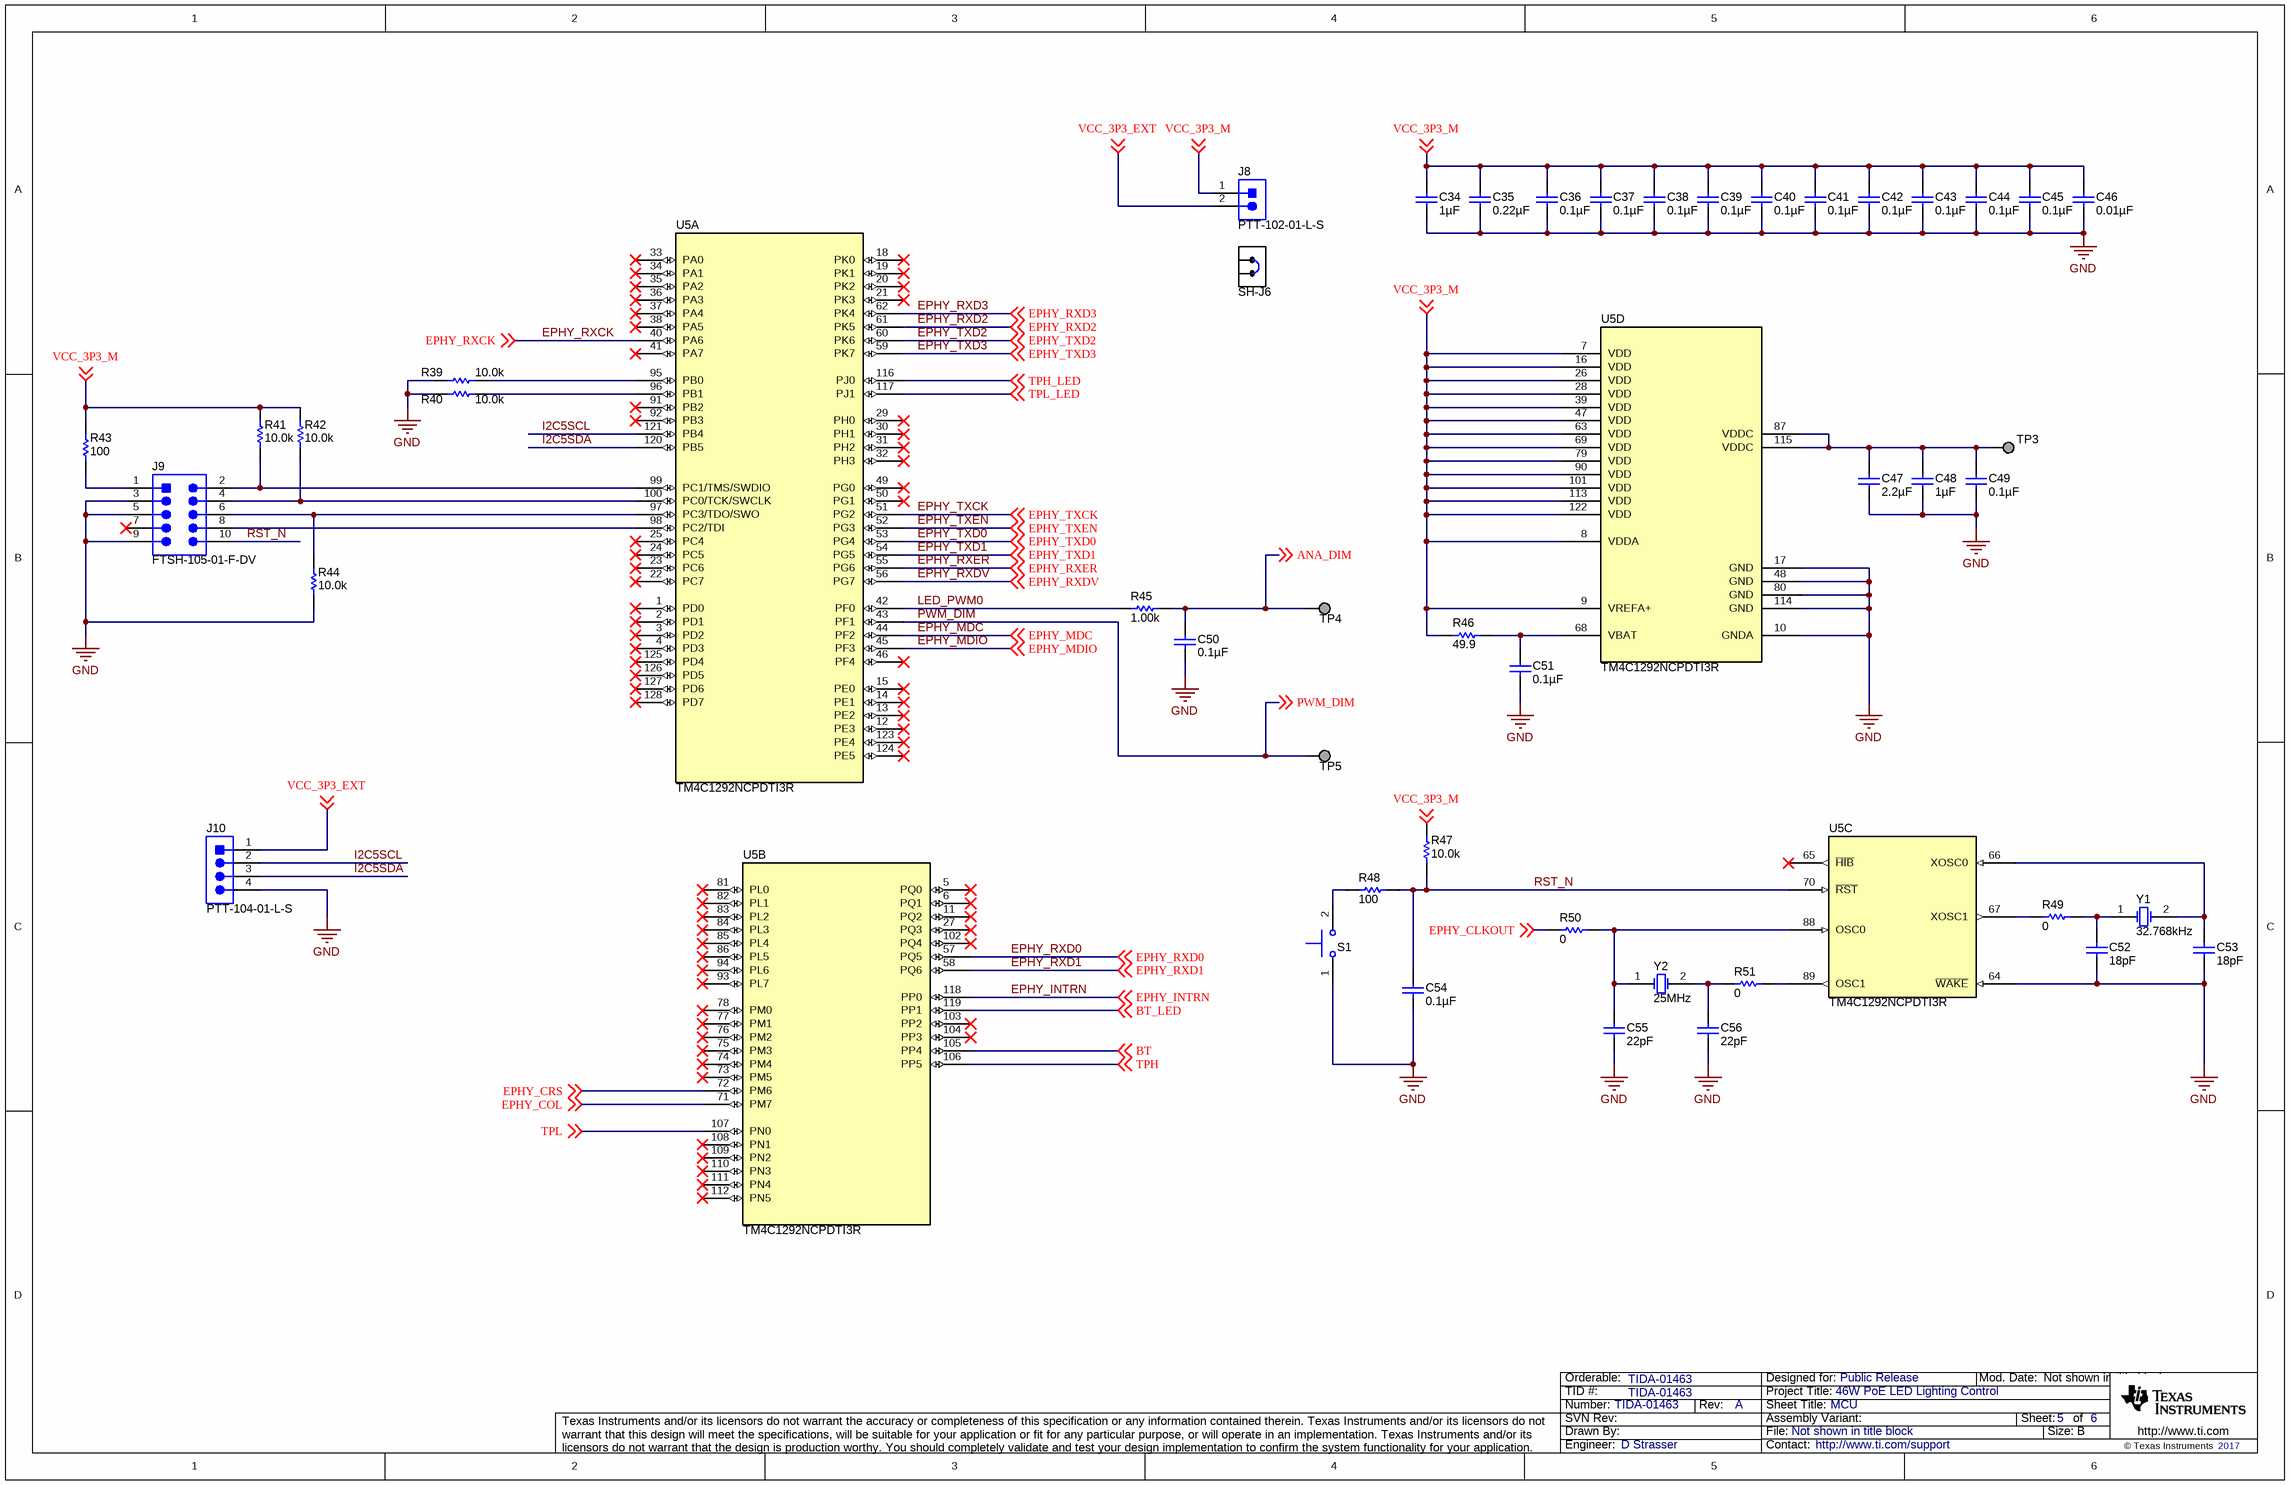
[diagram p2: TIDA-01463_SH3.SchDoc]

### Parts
C34  ValueDisplayed: 1µF  [0402]  (hidden comment: C1005X5R1A105K050BB)
C35  ValueDisplayed: 0.22µF  [0603]  (hidden comment: 885012206048)
C36  ValueDisplayed: 0.1µF  [0402]  (hidden comment: 885012205037)
C37  ValueDisplayed: 0.1µF  [0402]  (hidden comment: 885012205037)
C38  ValueDisplayed: 0.1µF  [0402]  (hidden comment: 885012205037)
C39  ValueDisplayed: 0.1µF  [0402]  (hidden comment: 885012205037)
C40  ValueDisplayed: 0.1µF  [0402]  (hidden comment: 885012205037)
C41  ValueDisplayed: 0.1µF  [0402]  (hidden comment: 885012205037)
C42  ValueDisplayed: 0.1µF  [0402]  (hidden comment: 885012205037)
C43  ValueDisplayed: 0.1µF  [0402]  (hidden comment: 885012205037)
C44  ValueDisplayed: 0.1µF  [0402]  (hidden comment: 885012205037)
C45  ValueDisplayed: 0.1µF  [0402]  (hidden comment: 885012205037)
C46  ValueDisplayed: 0.01µF  [0402]  (hidden comment: 885012205031)
C47  ValueDisplayed: 2.2µF  [0402]  (hidden comment: 885012105013)
C48  ValueDisplayed: 1µF  [0402]  (hidden comment: C1005X5R1A105K050BB)
C49  ValueDisplayed: 0.1µF  [0402]  (hidden comment: 885012205037)
C50  ValueDisplayed: 0.1µF  [0603]  (hidden comment: 885012206046)
C51  ValueDisplayed: 0.1µF  [0402]  (hidden comment: 885012205037)
C52  ValueDisplayed: 18pF  [0402]  (hidden comment: GRM1555C1H180JA01D)
C53  ValueDisplayed: 18pF  [0402]  (hidden comment: GRM1555C1H180JA01D)
C54  ValueDisplayed: 0.1µF  [0402]  (hidden comment: 885012205037)
C55  ValueDisplayed: 22pF  [0402]  (hidden comment: GRM1555C1H220JA01D)
C56  ValueDisplayed: 22pF  [0402]  (hidden comment: GRM1555C1H220JA01D)
J8  PTT-102-01-L-S  [Samtec_PTT-102-01-x-S]
J9  FTSH-105-01-F-DV  [Samtec_FTSH-105-01-x-DV]
J10  PTT-104-01-L-S  [Samtec_PTT-104-01-x-S]
R39  ValueDisplayed: 10.0k  [0402]  (hidden comment: CRCW040210K0FKED)
R40  ValueDisplayed: 10.0k  [0402]  (hidden comment: CRCW040210K0FKED)
R41  ValueDisplayed: 10.0k  [0402]  (hidden comment: CRCW040210K0FKED)
R42  ValueDisplayed: 10.0k  [0402]  (hidden comment: CRCW040210K0FKED)
R43  ValueDisplayed: 100  [0402]  (hidden comment: ERJ-2RKF1000X)
R44  ValueDisplayed: 10.0k  [0402]  (hidden comment: CRCW040210K0FKED)
R45  ValueDisplayed: 1.00k  [0603]  (hidden comment: CRCW06031K00FKEA)
R46  ValueDisplayed: 49.9  [0402]  (hidden comment: CRCW040249R9FKED)
R47  ValueDisplayed: 10.0k  [0402]  (hidden comment: CRCW040210K0FKED)
R48  ValueDisplayed: 100  [0402]  (hidden comment: ERJ-2RKF1000X)
R49  ValueDisplayed: 0  [0402]  (hidden comment: ERJ-2GE0R00X)
R50  ValueDisplayed: 0  [0402]  (hidden comment: ERJ-2GE0R00X)
R51  ValueDisplayed: 0  [0402]  (hidden comment: ERJ-2GE0R00X)
S1  SKRKAEE010  [SW_SKRKAEE010]  (value not drawn)
SH-J6  2SN-BK-G  [2SN-BK-G]  (value not drawn)
TP3  TESTPOINT  [PAD_1MM_SQUARE]  (value not drawn)  (no BOM)
TP4  TESTPOINT  [PAD_1MM_SQUARE]  (value not drawn)  (no BOM)
TP5  TESTPOINT  [PAD_1MM_SQUARE]  (value not drawn)  (no BOM)
U5  TM4C1292NCPDTI3R  [PDT0128A]  (parts A,B,C,D of 4)
Y1  Frequency: 32.768kHz  [XTAL_ABS07]  (hidden comment: ABS07-32.768KHZ-9-T)
Y2  Frequency: 25MHz  [NDK_NX5032GA]  (hidden comment: NX5032GA-25.000M-STD-CSK-4)

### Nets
GND: C34.2 C35.2 C36.2 C37.2 C38.2 C39.2 C40.2 C41.2 C42.2 C43.2 C44.2 C45.2 C46.2 C47.2 C48.2 C49.2 C50.2 C51.2 C52.2 C53.2 C54.2 C55.2 C56.2 J9.3 J9.5 J9.9 J10.4 R39.2 R40.2 R44.1 S1.1 U5.10(GNDA) U5.17(GND) U5.48(GND) U5.64(~{WAKE}) U5.80(GND) U5.114(GND)
ANA_DIM: C50.1 R45.2 TP4.1 ; off-sheet ANA_DIM
BT: U5.105(PP4) ; off-sheet BT
BT_LED: U5.119(PP1) ; off-sheet BT_LED
EPHY_CLKOUT: R50.1 ; off-sheet EPHY_CLKOUT
EPHY_COL: U5.71(PM7) ; off-sheet EPHY_COL
EPHY_CRS: U5.72(PM6) ; off-sheet EPHY_CRS
EPHY_INTRN: U5.118(PP0) ; off-sheet EPHY_INTRN
EPHY_MDC: U5.44(PF2) ; off-sheet EPHY_MDC
EPHY_MDIO: U5.45(PF3) ; off-sheet EPHY_MDIO
EPHY_RXCK: U5.40(PA6) ; off-sheet EPHY_RXCK
EPHY_RXD0: U5.57(PQ5) ; off-sheet EPHY_RXD0
EPHY_RXD1: U5.58(PQ6) ; off-sheet EPHY_RXD1
EPHY_RXD2: U5.61(PK5) ; off-sheet EPHY_RXD2
EPHY_RXD3: U5.62(PK4) ; off-sheet EPHY_RXD3
EPHY_RXDV: U5.56(PG7) ; off-sheet EPHY_RXDV
EPHY_RXER: U5.55(PG6) ; off-sheet EPHY_RXER
EPHY_TXCK: U5.51(PG2) ; off-sheet EPHY_TXCK
EPHY_TXD0: U5.53(PG4) ; off-sheet EPHY_TXD0
EPHY_TXD1: U5.54(PG5) ; off-sheet EPHY_TXD1
EPHY_TXD2: U5.60(PK6) ; off-sheet EPHY_TXD2
EPHY_TXD3: U5.59(PK7) ; off-sheet EPHY_TXD3
EPHY_TXEN: U5.52(PG3) ; off-sheet EPHY_TXEN
I2C5SCL: J10.2 U5.121(PB4)
I2C5SDA: J10.3 U5.120(PB5)
LED_PWM0: R45.1 U5.42(PF0)
PWM_DIM: TP5.1 U5.43(PF1) ; off-sheet PWM_DIM
RST_N: C54.1 J9.10 R47.1 R48.2 U5.70(~{RST})
TPH: U5.106(PP5) ; off-sheet TPH
TPH_LED: U5.116(PJ0) ; off-sheet TPH_LED
TPL: U5.107(PN0) ; off-sheet TPL
TPL_LED: U5.117(PJ1) ; off-sheet TPL_LED
VCC_3P3_EXT: J8.2 J10.1 ; off-sheet VCC_3P3_EXT
VCC_3P3_M: C34.1 C35.1 C36.1 C37.1 C38.1 C39.1 C40.1 C41.1 C42.1 C43.1 C44.1 C45.1 C46.1 J8.1 R41.2 R42.2 R43.2 R46.1 R47.2 U5.7(VDD) U5.8(VDDA) U5.9(VREFA+) U5.16(VDD) U5.26(VDD) U5.28(VDD) U5.39(VDD) U5.47(VDD) U5.63(VDD) U5.69(VDD) U5.79(VDD) U5.90(VDD) U5.101(VDD) U5.113(VDD) U5.122(VDD) ; off-sheet VCC_3P3_M
NetC47_1: C47.1 C48.1 C49.1 TP3.1 U5.87(VDDC) U5.115(VDDC)
NetC51_1: C51.1 R46.2 U5.68(VBAT)
NetC52_1: C52.1 R49.2 Y1.1(OSC1)
NetC53_1: C53.1 U5.66(XOSC0) Y1.2(OSC2)
NetC55_1: C55.1 R50.2 U5.88(OSC0) Y2.1(OSC1)
NetC56_1: C56.1 R51.1 Y2.2(OSC2)
NetJ9_1: J9.1 R43.1
NetJ9_2: J9.2 R41.1 U5.99(PC1/TMS/SWDIO)
NetJ9_4: J9.4 R42.1 U5.100(PC0/TCK/SWCLK)
NetJ9_6: J9.6 R44.2 U5.97(PC3/TDO/SWO)
NetJ9_8: J9.8 U5.98(PC2/TDI)
NetR39_1: R39.1 U5.95(PB0)
NetR40_1: R40.1 U5.96(PB1)
NetR48_1: R48.1 S1.2
NetR49_1: R49.1 U5.67(XOSC1)
NetR51_2: R51.2 U5.89(OSC1)

Not connected (* = marked no-connect by the designer): J9 7*; U5 1(PD0)* 2(PD1)* 3(PD2)* 4(PD3)* 5(PQ0)* 6(PQ1)* 11(PQ2)* 12(PE3)* 13(PE2)* 14(PE1)* 15(PE0)* 18(PK0)* 19(PK1)* 20(PK2)* 21(PK3)* 22(PC7)* 23(PC6)* 24(PC5)* 25(PC4)* 27(PQ3)* 29(PH0)* 30(PH1)* 31(PH2)* 32(PH3)* 33(PA0)* 34(PA1)* 35(PA2)* 36(PA3)* 37(PA4)* 38(PA5)* 41(PA7)* 46(PF4)* 49(PG0)* 50(PG1)* 65(~{HIB})* 73(PM5)* 74(PM4)* 75(PM3)* 76(PM2)* 77(PM1)* 78(PM0)* 81(PL0)* 82(PL1)* 83(PL2)* 84(PL3)* 85(PL4)* 86(PL5)* 91(PB2)* 92(PB3)* 93(PL7)* 94(PL6)* 102(PQ4)* 103(PP2)* 104(PP3)* 108(PN1)* 109(PN2)* 110(PN3)* 111(PN4)* 112(PN5)* 123(PE4)* 124(PE5)* 125(PD4)* 126(PD5)* 127(PD6)* 128(PD7)*

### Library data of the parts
C34 C48 = C1005X5R1A105K050BB: CAP, CERM, 1 µF, 10 V, +/- 10%, X5R, 0402; Manufacturer: TDK; Polarized: N; CompType: Capacitor; Value: 1uF; U/M: EA; Cap_F: 0.000001; Tolerance_%: 10; Value1: Unknown; Value2: 10V; TaMin_C: -55; TaMax_C: 85; SizeArea_mm2: 0.5; SizeAreaWB_mm2: 3; SizeX_mm: 1; SizeZ_mm: 0.6; AEC Category: Q200
C35 = 885012206048: CAP, CERM, 0.22 µF, 16 V, +/- 10%, X7R, 0603; Manufacturer: Wurth Elektronik; Polarized: N; CompType: Capacitor; Value: 0.22uF; U/M: EA; Cap_F: 0.00000022; Tolerance_%: 10; Value1: Unknown; VDC_V: 16; Value2: 16V; TaMin_C: -55; TaMax_C: 125; SizeArea_mm2: 1.28; SizeAreaWB_mm2: 4.68; SizeX_mm: 1.6; SizeY_mm: 0.8; SizeZ_mm: 1; AEC Category: Q200
C36-C45 C49 C51 C54 = 885012205037: CAP, CERM, 0.1 µF, 16 V, +/- 10%, X7R, 0402; Manufacturer: Wurth Elektronik; Polarized: N; CompType: Capacitor; Value: 0.1uF; U/M: EA; Cap_F: 0.0000001; Tolerance_%: 10; Value1: Unknown; VDC_V: 16; Value2: 16V; TaMin_C: -55; TaMax_C: 125; SizeArea_mm2: 0.5; SizeAreaWB_mm2: 3; SizeX_mm: 1; SizeZ_mm: 0.6; AEC Category: Q200
C46 = 885012205031: CAP, CERM, 0.01 µF, 16 V, +/- 10%, X7R, 0402; Manufacturer: Wurth Elektronik; Polarized: N; CompType: Capacitor; Value: 0.01uF; U/M: EA; Cap_F: 0.00000001; Tolerance_%: 10; Value1: Unknown; VDC_V: 16; Value2: 16V; TaMin_C: -55; TaMax_C: 125; SizeArea_mm2: 0.5; SizeAreaWB_mm2: 3; SizeX_mm: 1; SizeZ_mm: 0.6; AEC Category: Q200
C47 = 885012105013: CAP, CERM, 2.2 µF, 10 V, +/- 20%, X5R, 0402; Manufacturer: Wurth Elektronik; Polarized: N; CompType: Capacitor; Value: 2.2uF; U/M: EA; Cap_F: 0.0000022; Tolerance_%: 20; Value1: Unknown; VDC_V: 10; Value2: 10V; TaMin_C: -55; TaMax_C: 85; SizeArea_mm2: 0.5; SizeAreaWB_mm2: 3; SizeX_mm: 1; SizeZ_mm: 0.6; AEC Category: Q200
C50 = 885012206046: CAP, CERM, 0.1 µF, 16 V, +/- 10%, X7R, 0603; Manufacturer: Wurth Elektronik; Polarized: N; CompType: Capacitor; Value: 0.1uF; U/M: EA; Cap_F: 0.0000001; Tolerance_%: 10; Value1: Unknown; VDC_V: 16; Value2: 16V; TaMin_C: -55; TaMax_C: 125; SizeArea_mm2: 1.28; SizeAreaWB_mm2: 4.68; SizeX_mm: 1.6; SizeY_mm: 0.8; SizeZ_mm: 1; AEC Category: Q200
C52 C53 = GRM1555C1H180JA01D: CAP, CERM, 18 pF, 50 V, +/- 5%, C0G/NP0, 0402; Manufacturer: MuRata; Polarized: N; CompType: Capacitor; Value: 18pF; U/M: EA; Cap_F: 0.000000000018; Tolerance_%: 5; Value1: Unknown; VDC_V: 50; Value2: 50V; TaMin_C: -55; TaMax_C: 125; SizeArea_mm2: 0.5; SizeAreaWB_mm2: 3; SizeX_mm: 1; SizeZ_mm: 0.6; AEC Category: Q200
C55 C56 = GRM1555C1H220JA01D: CAP, CERM, 22 pF, 50 V, +/- 5%, C0G/NP0, 0402; Manufacturer: MuRata; Polarized: N; CompType: Capacitor; Value: 22pF; U/M: EA; Cap_F: 0.000000000022; Tolerance_%: 5; Value1: Unknown; VDC_V: 50; Value2: 50V; TaMin_C: -55; TaMax_C: 125; SizeArea_mm2: 0.5; SizeAreaWB_mm2: 3; SizeX_mm: 1; SizeZ_mm: 0.6; AEC Category: Q200
J8 = PTT-102-01-L-S: as J2 on sheet TIDA-01463_SH2
J9 = FTSH-105-01-F-DV: Header, 1.27mm, 5x2, Gold, Black, SMT; Manufacturer: Samtec; SymbolCreator: a0412235; Pitch_mm: 1.27; Gender: Male; Row_Count: 2; Current_A: 3.3; Cert_CSA: Y
J10 = PTT-104-01-L-S: Header, 2mm, 4x1, Gold, TH; Manufacturer: Samtec; SymbolCreator: a0412235; Pitch_mm: 2; Gender: Male; Shrouded: N; Row_Count: 1; Current_A: 2.9; Cert_UL: Y
R39-R42 R44 R47 = CRCW040210K0FKED: as R34 on sheet TIDA-01463_SH2
R43 R48 = ERJ-2RKF1000X: RES, 100, 1%, 0.1 W, 0402; Manufacturer: Panasonic; CompType: Resistor; Value: 100; Value_Code: 100R; Tolerance_%: 1; Power_W: 0.1; Value2: 0.1W; VDC_V: 50; TempCo: 100 ppm/C; SizeArea_mm2: 0.5; SizeZ_mm: 0.6; EIA_Code: E96; U/M: EA; AEC Category: Q200
R45 = CRCW06031K00FKEA: RES, 1.00 k, 1%, 0.1 W, 0603; Manufacturer: Vishay-Dale; CompType: Resistor; Value: 1.00k; Res_ohm: 1000; Value_Code: 1k00; Tolerance_%: 1; Power_W: 0.1; Value2: 0.1W; VDC_V: 75; TempCo: 100 ppm/C; SizeArea_mm2: 1.28; SizeX_mm: 1.6; SizeY_mm: 0.8; EIA_Code: E96; U/M: EA; AEC Category: Q200
R46 = CRCW040249R9FKED: RES, 49.9, 1%, 0.063 W, 0402; Manufacturer: Vishay-Dale; CompType: Resistor; Value: 49.9; Value_Code: 49R9; Tolerance_%: 1; Power_W: 0.063; Value2: 0.063W; VDC_V: 50; TempCo: 100 ppm/C; SizeArea_mm2: 0.5; SizeZ_mm: 0.6; EIA_Code: E96; U/M: EA; AEC Category: Q200
R49-R51 = ERJ-2GE0R00X: as R28 on sheet TIDA-01463_SH2
S1 = SKRKAEE010: Switch, Push Button, SMD; Manufacturer: Alps; SymbolCreator: a0412235; Circuit: SPST-NO; VDC_V: 12; SwitchFunction: Off-Mom; PositionCount: 1; CurrentRating_mA: 50
SH-J6 = 2SN-BK-G: as SH-J1 on sheet TIDA-01463_SH2
TP3-TP5 = PAD_1MM_SQUARE: as TP6 on sheet TIDA-01463_SH2
U5 = TM4C1292NCPDTI3R: Tiva C Series Microcontroller, PDT0128A; Manufacturer: Texas Instruments; SymbolCreator: Altium; SizeArea_mm2: 256; SizeAreaWB_mm2: 324; SizeX_mm: 16; SizeZ_mm: 1.2; CompType: IC; U/M: EA
Y1 = ABS07-32.768KHZ-9-T: CRYSTAL, 32.768KHZ, 9PF, SMD; Manufacturer: Abracon Corporation; SymbolCreator: a0412235; U/M: EA; TaMin_C: -40; TaMax_C: 85; Frequency Stability: ±20ppm
Y2 = NX5032GA-25.000M-STD-CSK-4: Crystal, 25MHz,  SMD; Manufacturer: NDK; SymbolCreator: a0412235; U/M: EA; TaMin_C: -40; TaMax_C: 150; Frequency Stability: ±30ppm

## Sheet TIDA-01463_SH4.SchDoc: PHY
size 431 x 279 mm; Date: Not shown in title block; ApprovedBy: Not shown in title block; CheckedBy: Not shown in title block; Author: Not shown in title block; CompanyName: Not shown in title block; Engineer: Not shown in title block; Organization: Not shown in title block; Address1: Not shown in title block; Address2: Not shown in title block; Address3: Not shown in title block; Address4: Not shown in title block; DocumentNumber: 6; Revision: Use project parameter SCH_Rev; SheetNumber: 6; SheetTotal: 6; PageSetup: Record=PageOptions¦CenterHorizontal=True¦CenterVertical=True¦PrintScale=1.00¦XCorrection=1.00¦YCorrection=1.00¦PrintKind=0¦BorderSize=5000000¦LeftOffset=0¦BottomOffset=0¦Orientation=2¦PaperLength=1000¦PaperWidth=1000¦Scale=100¦PaperSource=15¦PrintQuality=600¦MediaType=1¦DitherType=10¦PaperKind=Letter¦PrintScaleMode=1
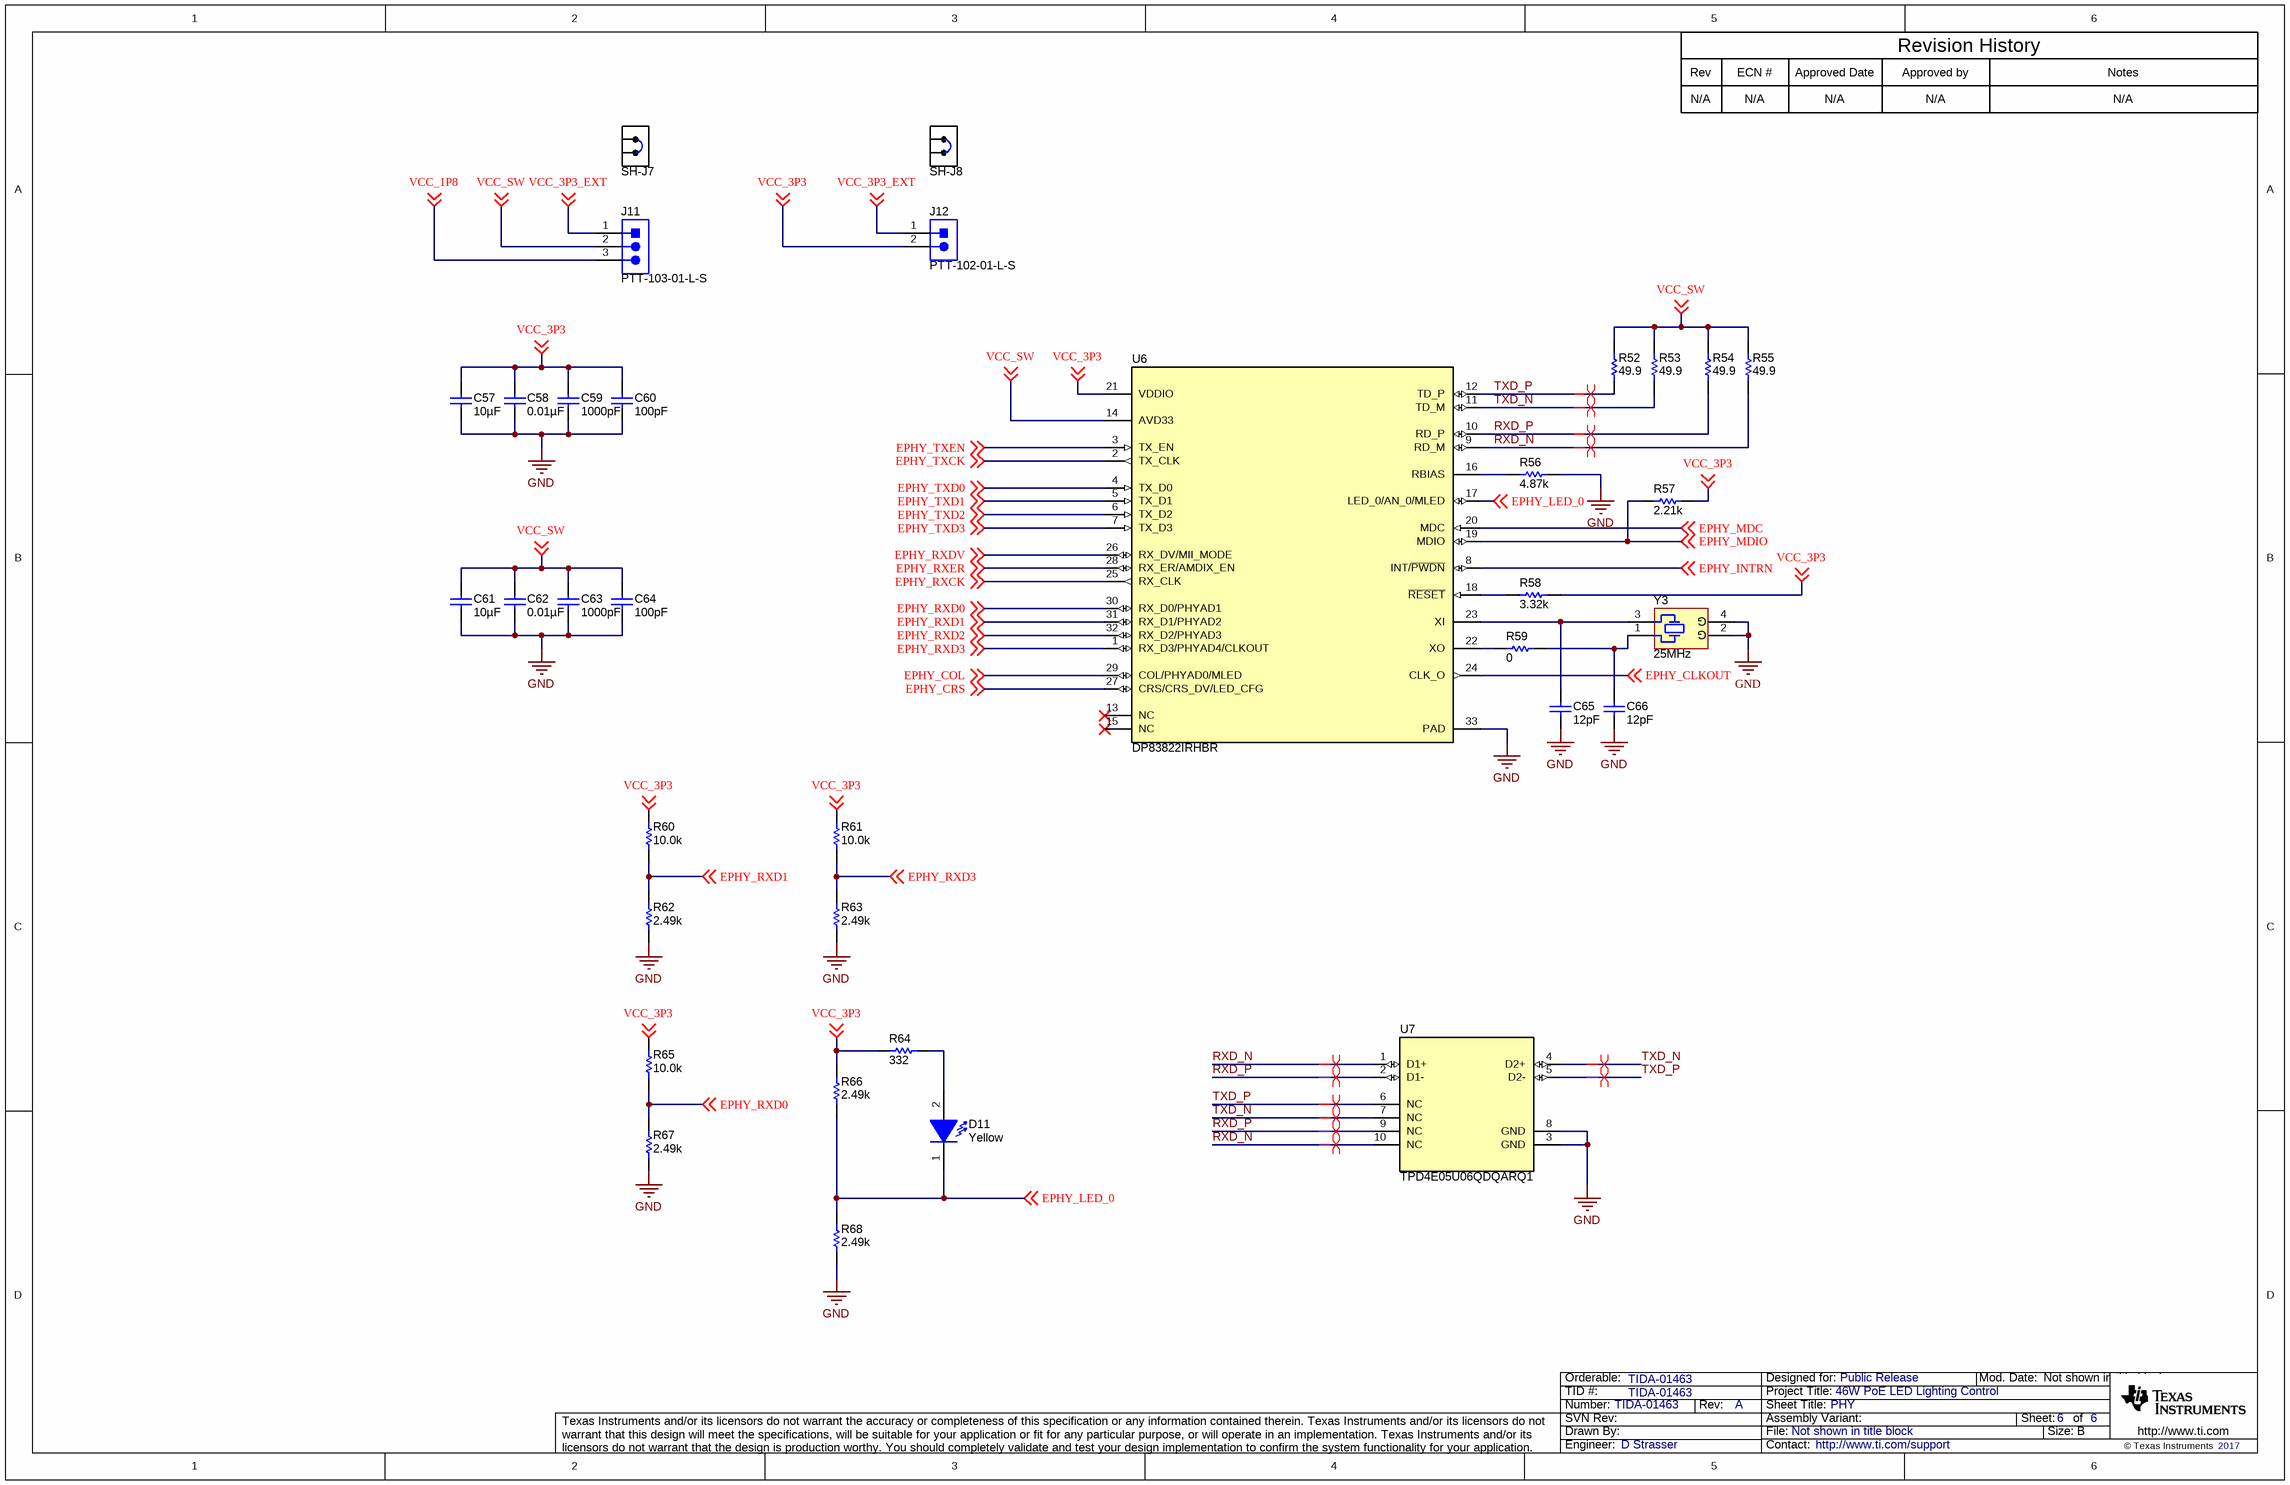
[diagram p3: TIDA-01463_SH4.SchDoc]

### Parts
C57  ValueDisplayed: 10µF  [1210_280]  (hidden comment: CGA6P1X7R1E106M250AC)
C58  ValueDisplayed: 0.01µF  [0402]  (hidden comment: 885012205031)
C59  ValueDisplayed: 1000pF  [0402]  (hidden comment: 885012205061)
C60  ValueDisplayed: 100pF  [0402]  (hidden comment: 885012005061)
C61  ValueDisplayed: 10µF  [1210_280]  (hidden comment: CGA6P1X7R1E106M250AC)
C62  ValueDisplayed: 0.01µF  [0402]  (hidden comment: 885012205031)
C63  ValueDisplayed: 1000pF  [0402]  (hidden comment: 885012205061)
C64  ValueDisplayed: 100pF  [0402]  (hidden comment: 885012005061)
C65  ValueDisplayed: 12pF  [0402]  (hidden comment: C0402C120J3GACAUTO)
C66  ValueDisplayed: 12pF  [0402]  (hidden comment: C0402C120J3GACAUTO)
D11  value Yellow  [19-21_Yellow]  (hidden comment: 19-21UYC/S530-A4/TR8)
J11  PTT-103-01-L-S  [Samtec_PTT-103-01-x-S]
J12  PTT-102-01-L-S  [Samtec_PTT-102-01-x-S]
R52  ValueDisplayed: 49.9  [0402]  (hidden comment: CRCW040249R9FKED)
R53  ValueDisplayed: 49.9  [0402]  (hidden comment: CRCW040249R9FKED)
R54  ValueDisplayed: 49.9  [0402]  (hidden comment: CRCW040249R9FKED)
R55  ValueDisplayed: 49.9  [0402]  (hidden comment: CRCW040249R9FKED)
R56  ValueDisplayed: 4.87k  [0402]  (hidden comment: CRCW04024K87FKED)
R57  ValueDisplayed: 2.21k  [0402]  (hidden comment: CRCW04022K21FKED)
R58  ValueDisplayed: 3.32k  [0402]  (hidden comment: CRCW04023K32FKED)
R59  ValueDisplayed: 0  [0402]  (hidden comment: ERJ-2GE0R00X)
R60  ValueDisplayed: 10.0k  [0402]  (hidden comment: CRCW040210K0FKED)
R61  ValueDisplayed: 10.0k  [0402]  (hidden comment: CRCW040210K0FKED)
R62  ValueDisplayed: 2.49k  [0402]  (hidden comment: CRCW04022K49FKED)
R63  ValueDisplayed: 2.49k  [0402]  (hidden comment: CRCW04022K49FKED)
R64  ValueDisplayed: 332  [0402]  (hidden comment: CRCW0402332RFKED)
R65  ValueDisplayed: 10.0k  [0402]  (hidden comment: CRCW040210K0FKED)
R66  ValueDisplayed: 2.49k  [0402]  (hidden comment: CRCW04022K49FKED)
R67  ValueDisplayed: 2.49k  [0402]  (hidden comment: CRCW04022K49FKED)
R68  ValueDisplayed: 2.49k  [0402]  (hidden comment: CRCW04022K49FKED)
SH-J7  2SN-BK-G  [2SN-BK-G]  (value not drawn)
SH-J8  2SN-BK-G  [2SN-BK-G]  (value not drawn)
U6  DP83822IRHBR  [RHB0032B]
U7  TPD4E05U06QDQARQ1  [DQA0010A]
Y3  Frequency: 25MHz  [Kyocera_CX3225CA]  (hidden comment: CX3225CA25000D0HSSCC)

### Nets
GND: C57.2 C58.2 C59.2 C60.2 C61.2 C62.2 C63.2 C64.2 C65.2 C66.2 R56.2 R62.1 R63.1 R67.1 R68.1 U6.33(PAD) U7.3(GND) U7.8(GND) Y3.2(GND) Y3.4(GND)
EPHY_CLKOUT: U6.24(CLK_O) ; off-sheet EPHY_CLKOUT
EPHY_COL: U6.29(COL/PHYAD0/MLED) ; off-sheet EPHY_COL
EPHY_CRS: U6.27(CRS/CRS_DV/LED_CFG) ; off-sheet EPHY_CRS
EPHY_INTRN: U6.8(INT/~{PWDN}) ; off-sheet EPHY_INTRN
EPHY_LED_0: D11.1(K) R66.1 R68.2 U6.17(LED_0/AN_0/MLED) ; off-sheet EPHY_LED_0
EPHY_MDC: U6.20(MDC) ; off-sheet EPHY_MDC
EPHY_MDIO: R57.2 U6.19(MDIO) ; off-sheet EPHY_MDIO
EPHY_RXCK: U6.25(RX_CLK) ; off-sheet EPHY_RXCK
EPHY_RXD0: R65.1 R67.2 U6.30(RX_D0/PHYAD1) ; off-sheet EPHY_RXD0
EPHY_RXD1: R60.1 R62.2 U6.31(RX_D1/PHYAD2) ; off-sheet EPHY_RXD1
EPHY_RXD2: U6.32(RX_D2/PHYAD3) ; off-sheet EPHY_RXD2
EPHY_RXD3: R61.1 R63.2 U6.1(RX_D3/PHYAD4/CLKOUT) ; off-sheet EPHY_RXD3
EPHY_RXDV: U6.26(RX_DV/MII_MODE) ; off-sheet EPHY_RXDV
EPHY_RXER: U6.28(RX_ER/AMDIX_EN) ; off-sheet EPHY_RXER
EPHY_TXCK: U6.2(TX_CLK) ; off-sheet EPHY_TXCK
EPHY_TXD0: U6.4(TX_D0) ; off-sheet EPHY_TXD0
EPHY_TXD1: U6.5(TX_D1) ; off-sheet EPHY_TXD1
EPHY_TXD2: U6.6(TX_D2) ; off-sheet EPHY_TXD2
EPHY_TXD3: U6.7(TX_D3) ; off-sheet EPHY_TXD3
EPHY_TXEN: U6.3(TX_EN) ; off-sheet EPHY_TXEN
RXD_N: R55.1 U6.9(RD_M) U7.1(D1+) U7.10(NC)
RXD_P: R54.1 U6.10(RD_P) U7.2(D1-) U7.9(NC)
TXD_N: R53.1 U6.11(TD_M) U7.4(D2+) U7.7(NC)
TXD_P: R52.1 U6.12(TD_P) U7.5(D2-) U7.6(NC)
VCC_1P8: J11.3 ; off-sheet VCC_1P8
VCC_3P3: C57.1 C58.1 C59.1 C60.1 J12.2 R57.1 R58.2 R60.2 R61.2 R64.1 R65.2 R66.2 U6.21(VDDIO) ; off-sheet VCC_3P3
VCC_3P3_EXT: J11.1 J12.1 ; off-sheet VCC_3P3_EXT
VCC_SW: C61.1 C62.1 C63.1 C64.1 J11.2 R52.2 R53.2 R54.2 R55.2 U6.14(AVD33) ; off-sheet VCC_SW
NetC65_1: C65.1 U6.23(XI) Y3.3
NetC66_1: C66.1 R59.2 Y3.1
NetD11_2: D11.2(A) R64.2
NetR56_1: R56.1 U6.16(RBIAS)
NetR58_1: R58.1 U6.18(~{RESET})
NetR59_1: R59.1 U6.22(XO)

Not connected (* = marked no-connect by the designer): U6 13(NC)* 15(NC)*

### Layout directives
differential pair: RXD_N, RXD_P, TXD_N, TXD_P

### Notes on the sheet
- Rev
- N/A
- ECN #
- Approved Date
- Approved by
- Revision History
- Notes

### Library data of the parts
C57 C61 = CGA6P1X7R1E106M250AC: CAP, CERM, 10 µF, 25 V, +/- 20%, X7R, AEC-Q200 Grade 1, 1210; Manufacturer: TDK; Polarized: N; CompType: Capacitor; Value: 10uF; U/M: EA; Cap_F: 0.00001; Tolerance_%: 20; Value1: Unknown; VDC_V: 25; Value2: 25V; TaMin_C: -55; TaMax_C: 125; Cap_Case: 1210; AEC Category: Q200; AEC Qualified: Y; AEC Grade: 1
C58 C62 = 885012205031: CAP, CERM, 0.01 µF, 16 V, +/- 10%, X7R, 0402; Manufacturer: Wurth Elektronik; Polarized: N; CompType: Capacitor; Value: 0.01uF; U/M: EA; Cap_F: 0.00000001; Tolerance_%: 10; Value1: Unknown; VDC_V: 16; Value2: 16V; TaMin_C: -55; TaMax_C: 125; AEC Category: Q200; SizeArea_mm2: 0.5; SizeAreaWB_mm2: 3; SizeX_mm: 1; SizeZ_mm: 0.6
C59 C63 = 885012205061: CAP, CERM, 1000 pF, 50 V, +/- 10%, X7R, 0402; Manufacturer: Wurth Elektronik; Polarized: N; CompType: Capacitor; Value: 1000pF; U/M: EA; Cap_F: 0.000000001; Tolerance_%: 10; Value1: Unknown; VDC_V: 50; Value2: 50V; TaMin_C: -55; TaMax_C: 125; AEC Category: Q200; SizeArea_mm2: 0.5; SizeAreaWB_mm2: 3; SizeX_mm: 1; SizeZ_mm: 0.6
C60 C64 = 885012005061: CAP, CERM, 100 pF, 50 V, +/- 5%, C0G/NP0, 0402; Manufacturer: Wurth Elektronik; Polarized: N; CompType: Capacitor; Value: 100pF; U/M: EA; Cap_F: 0.0000000001; Tolerance_%: 5; Value1: Unknown; VDC_V: 50; Value2: 50V; TaMin_C: -55; TaMax_C: 125; AEC Category: Q200; SizeArea_mm2: 0.5; SizeAreaWB_mm2: 3; SizeX_mm: 1; SizeZ_mm: 0.6
C65 C66 = C0402C120J3GACAUTO: CAP, CERM, 12 pF, 25 V, +/- 5%, C0G/NP0, AEC-Q200 Grade 1, 0402; Manufacturer: Kemet; Polarized: N; CompType: Capacitor; Value: 12pF; U/M: EA; Cap_F: 0.000000000012; Tolerance_%: 5; Value1: Unknown; VDC_V: 25; Value2: 25V; TaMin_C: -55; TaMax_C: 125; AEC Category: Q200; AEC Qualified: Y; AEC Grade: 1
D11 = 19-21UYC/S530-A4/TR8: LED, Yellow, SMD; Manufacturer: Everlight; Type: AlInGaP; Vf_V: 2; Value2: 2V; Io_A: 0.02; Vr_V: 5; Ir_A: 1e-005; Tjmax_C: 85; Value1: W; Angle: 100; U/M: EA
J11 = PTT-103-01-L-S: as J3 on sheet TIDA-01463_SH2
J12 = PTT-102-01-L-S: as J2 on sheet TIDA-01463_SH2
R52-R55 = CRCW040249R9FKED: RES, 49.9, 1%, 0.063 W, 0402; Manufacturer: Vishay-Dale; CompType: Resistor; Value: 49.9; Value_Code: 49R9; Tolerance_%: 1; Power_W: 0.063; Value2: 0.063W; VDC_V: 50; TempCo: 100 ppm/C; EIA_Code: E96; U/M: EA
R56 = CRCW04024K87FKED: RES, 4.87 k, 1%, 0.063 W, 0402; Manufacturer: Vishay-Dale; CompType: Resistor; Value: 4.87k; Res_ohm: 4870; Value_Code: 4k87; Tolerance_%: 1; Power_W: 0.063; Value2: 0.063W; VDC_V: 50; TempCo: 100 ppm/C; SizeArea_mm2: 0.5; SizeZ_mm: 0.6; EIA_Code: E96; U/M: EA; AEC Category: Q200
R57 = CRCW04022K21FKED: RES, 2.21 k, 1%, 0.063 W, 0402; Manufacturer: Vishay-Dale; CompType: Resistor; Value: 2.21k; Res_ohm: 2210; Value_Code: 2k21; Tolerance_%: 1; Power_W: 0.063; Value2: 0.063W; VDC_V: 50; TempCo: 100 ppm/C; EIA_Code: E96; U/M: EA; AEC Category: Q200; SizeArea_mm2: 0.5; SizeZ_mm: 0.6
R58 = CRCW04023K32FKED: RES, 3.32 k, 1%, 0.063 W, 0402; Manufacturer: Vishay-Dale; CompType: Resistor; Value: 3.32k; Res_ohm: 3320; Value_Code: 3k32; Tolerance_%: 1; Power_W: 0.063; Value2: 0.063W; VDC_V: 50; TempCo: 100 ppm/C; SizeArea_mm2: 0.5; SizeZ_mm: 0.6; EIA_Code: E96; U/M: EA; AEC Category: Q200
R59 = ERJ-2GE0R00X: RES, 0, 5%, 0.063 W, 0402; Manufacturer: Panasonic; CompType: Resistor; Value: 0; Value_Code: 0000; Tolerance_%: 5; Power_W: 0.063; Value2: 0.063W; VDC_V: 50; TempCo: 600 ppm/C; EIA_Code: E24; U/M: EA; AEC Category: Q200; SizeArea_mm2: 0.5; SizeX_mm: 1; SizeZ_mm: 0.6
R60 R61 R65 = CRCW040210K0FKED: RES, 10.0 k, 1%, 0.063 W, 0402; Manufacturer: Vishay-Dale; CompType: Resistor; Value: 10.0k; Res_ohm: 10000; Value_Code: 10k0; Tolerance_%: 1; Power_W: 0.063; Value2: 0.063W; VDC_V: 50; TempCo: 100 ppm/C; EIA_Code: E96; U/M: EA; AEC Category: Q200
R62 R63 R66-R68 = CRCW04022K49FKED: RES, 2.49 k, 1%, 0.063 W, 0402; Manufacturer: Vishay-Dale; CompType: Resistor; Value: 2.49k; Res_ohm: 2490; Value_Code: 2k49; Tolerance_%: 1; Power_W: 0.063; Value2: 0.063W; VDC_V: 50; TempCo: 100 ppm/C; EIA_Code: E96; U/M: EA; AEC Category: Q200
R64 = CRCW0402332RFKED: RES, 332, 1%, 0.063 W, 0402; Manufacturer: Vishay-Dale; CompType: Resistor; Value: 332; Value_Code: 332R; Tolerance_%: 1; Power_W: 0.063; Value2: 0.063W; VDC_V: 50; TempCo: 100 ppm/C; SizeArea_mm2: 0.5; SizeZ_mm: 0.6; EIA_Code: E96; U/M: EA; AEC Category: Q200
SH-J7 SH-J8 = 2SN-BK-G: as SH-J1 on sheet TIDA-01463_SH2
U6 = CMP-0076010-2: Robust, Low Power 10/100 Ethernet Physical Layer Transceiver, RHB0032B (VQFN-32); Alternate PartNumber: DP83822IRHBT; Manufacturer: Texas Instruments; SizeZ_mm: 1.0; SizeX_mm: 5.0; SizeArea_mm2: 25.0; CompType: IC; U/M: EA; SizeAreaWB_mm2: 49.0
U7 = TPD4E05U06QDQARQ1: 1, 4, 6 CHANNEL PROTECTION SOLUTION FOR SUPER-SPEED (UP TO 6 GBPS) INTERFACE, DQA0010A; Manufacturer: Texas Instruments; SymbolCreator: a0411947; CompType: IC; U/M: EA
Y3 = CX3225CA25000D0HSSCC: Crystal, 25MHz, 8pF, SMD; Manufacturer: Kyocera; SymbolCreator: a0411947; U/M: EA; TaMin_C: -40; TaMax_C: 125; Frequency Stability: ±50ppm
